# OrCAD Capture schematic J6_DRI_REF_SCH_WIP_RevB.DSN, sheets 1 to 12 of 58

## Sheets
1 SH01 - TITLE PAGE: title: Virtual J6 DRI Board; rev: B; note: tbd
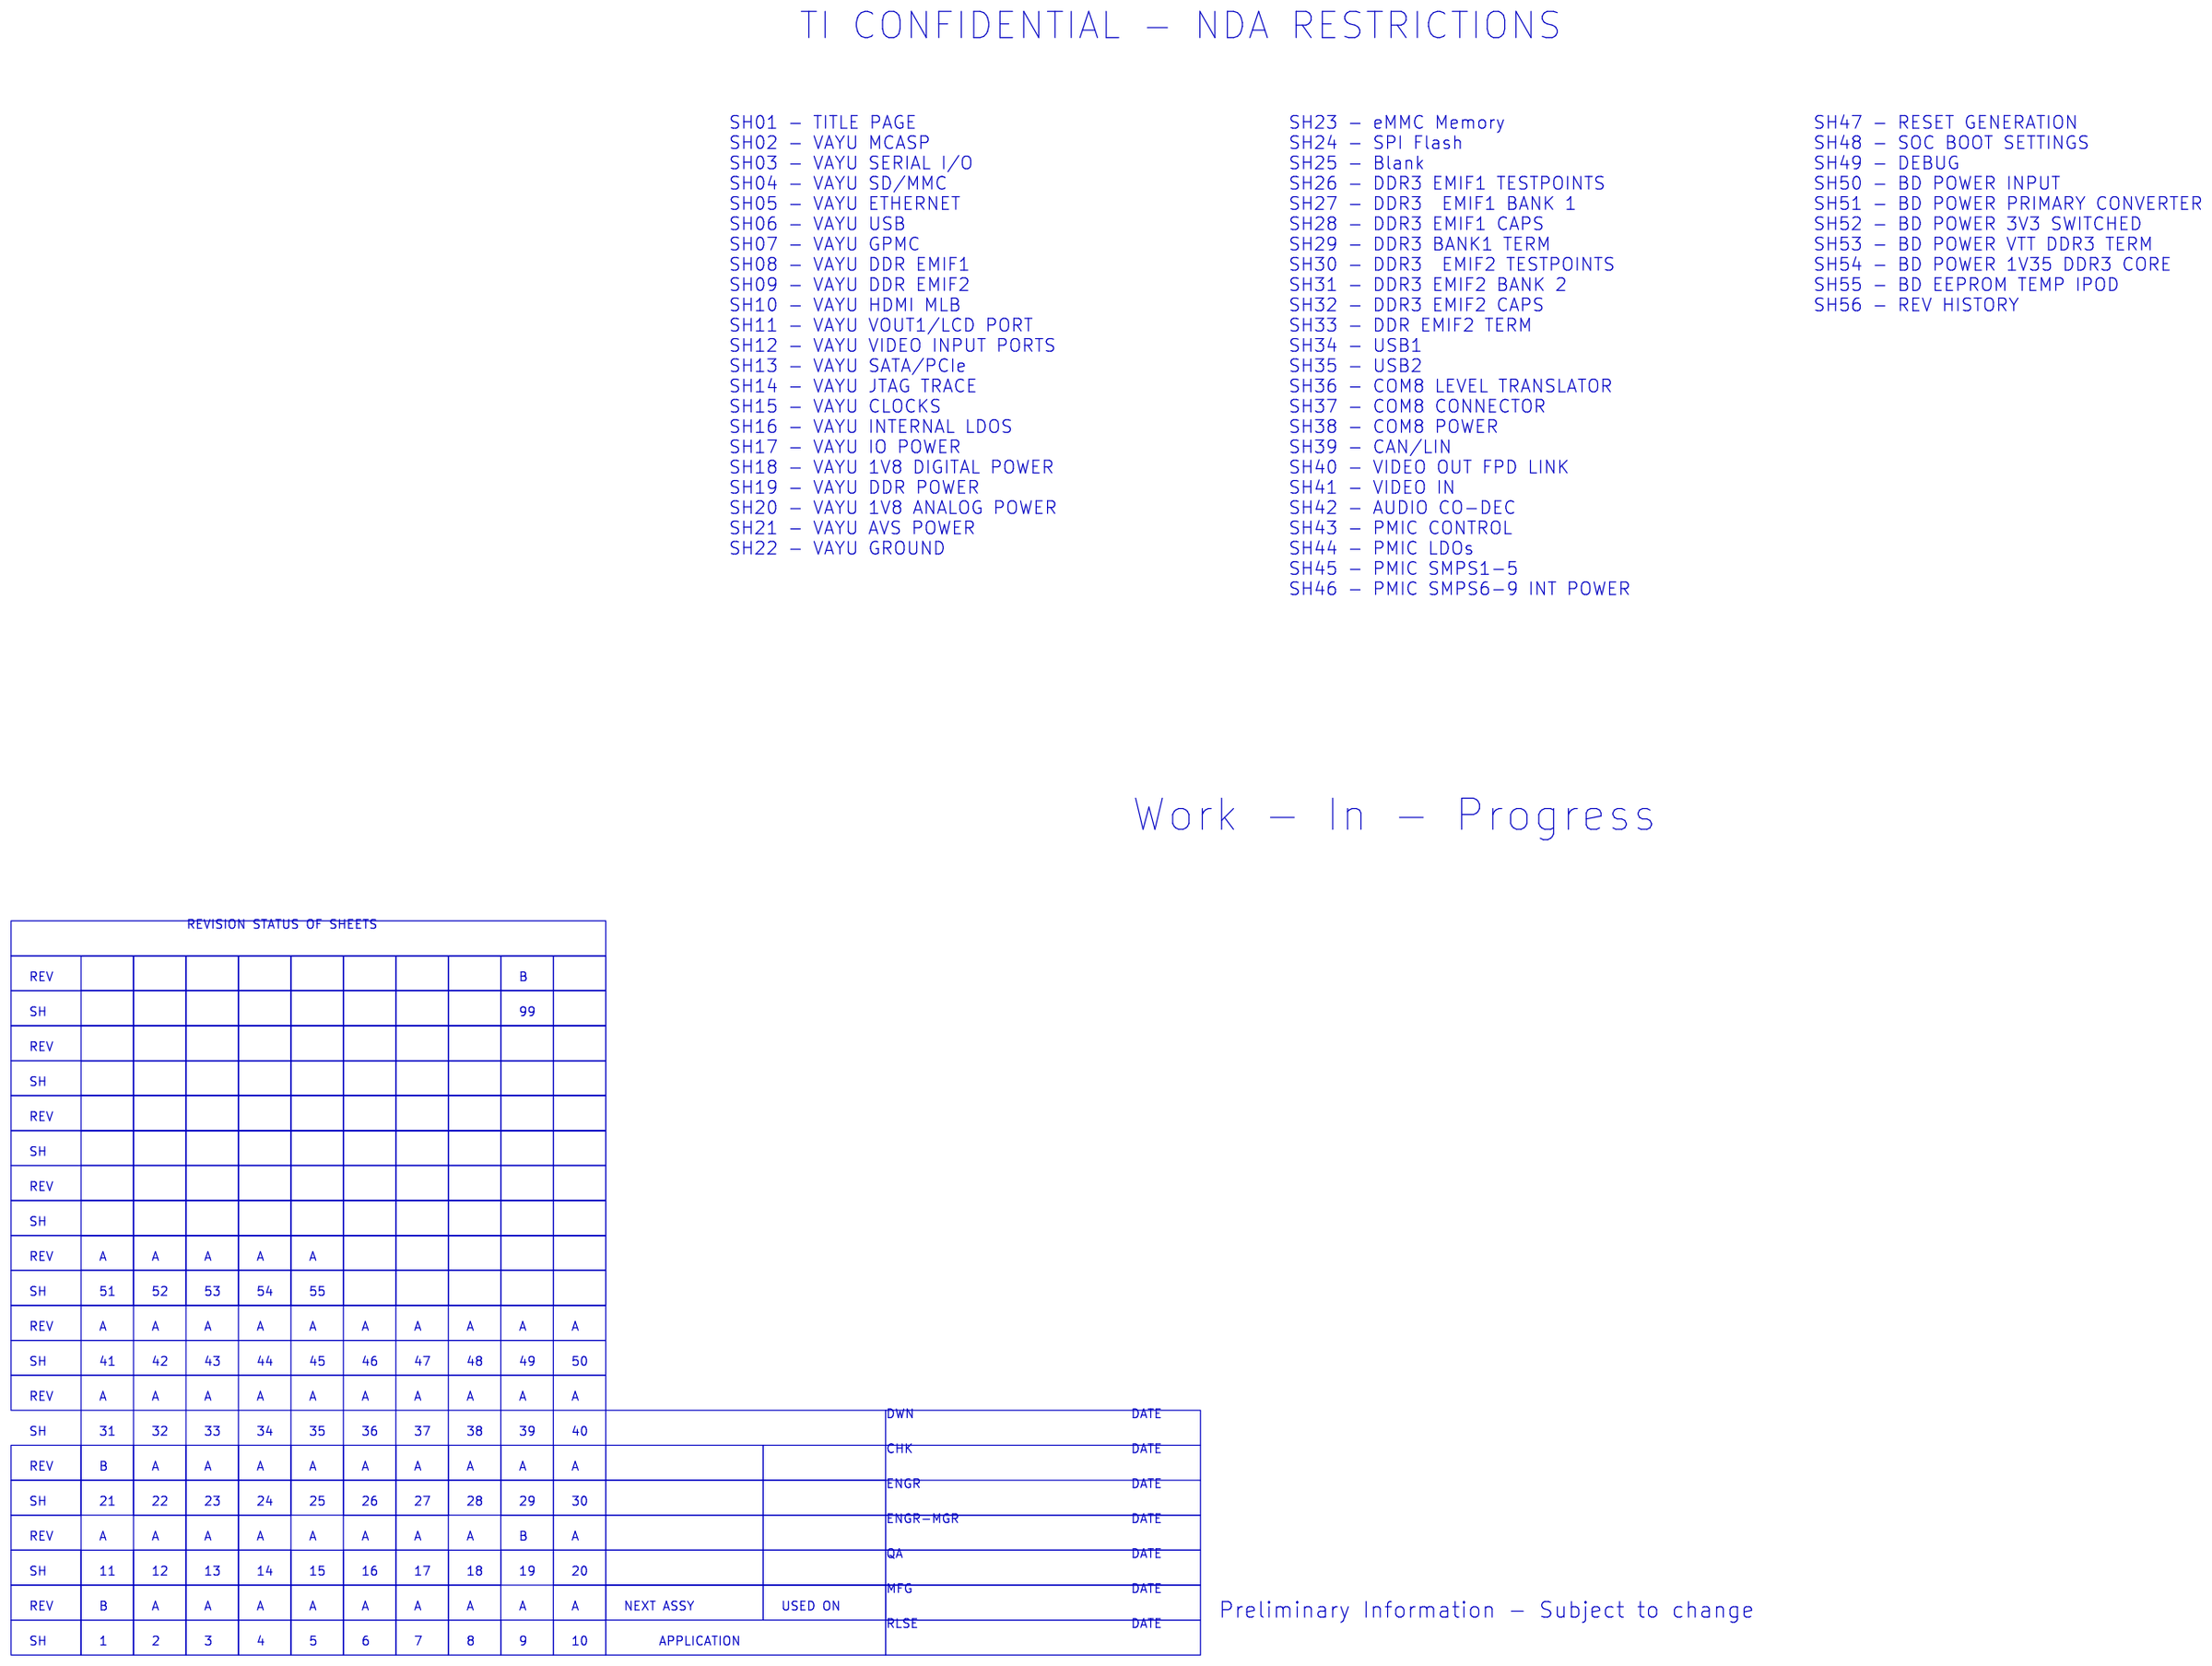
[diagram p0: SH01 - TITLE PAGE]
2 SH02 - VAYU MCASP: size B; rev: A
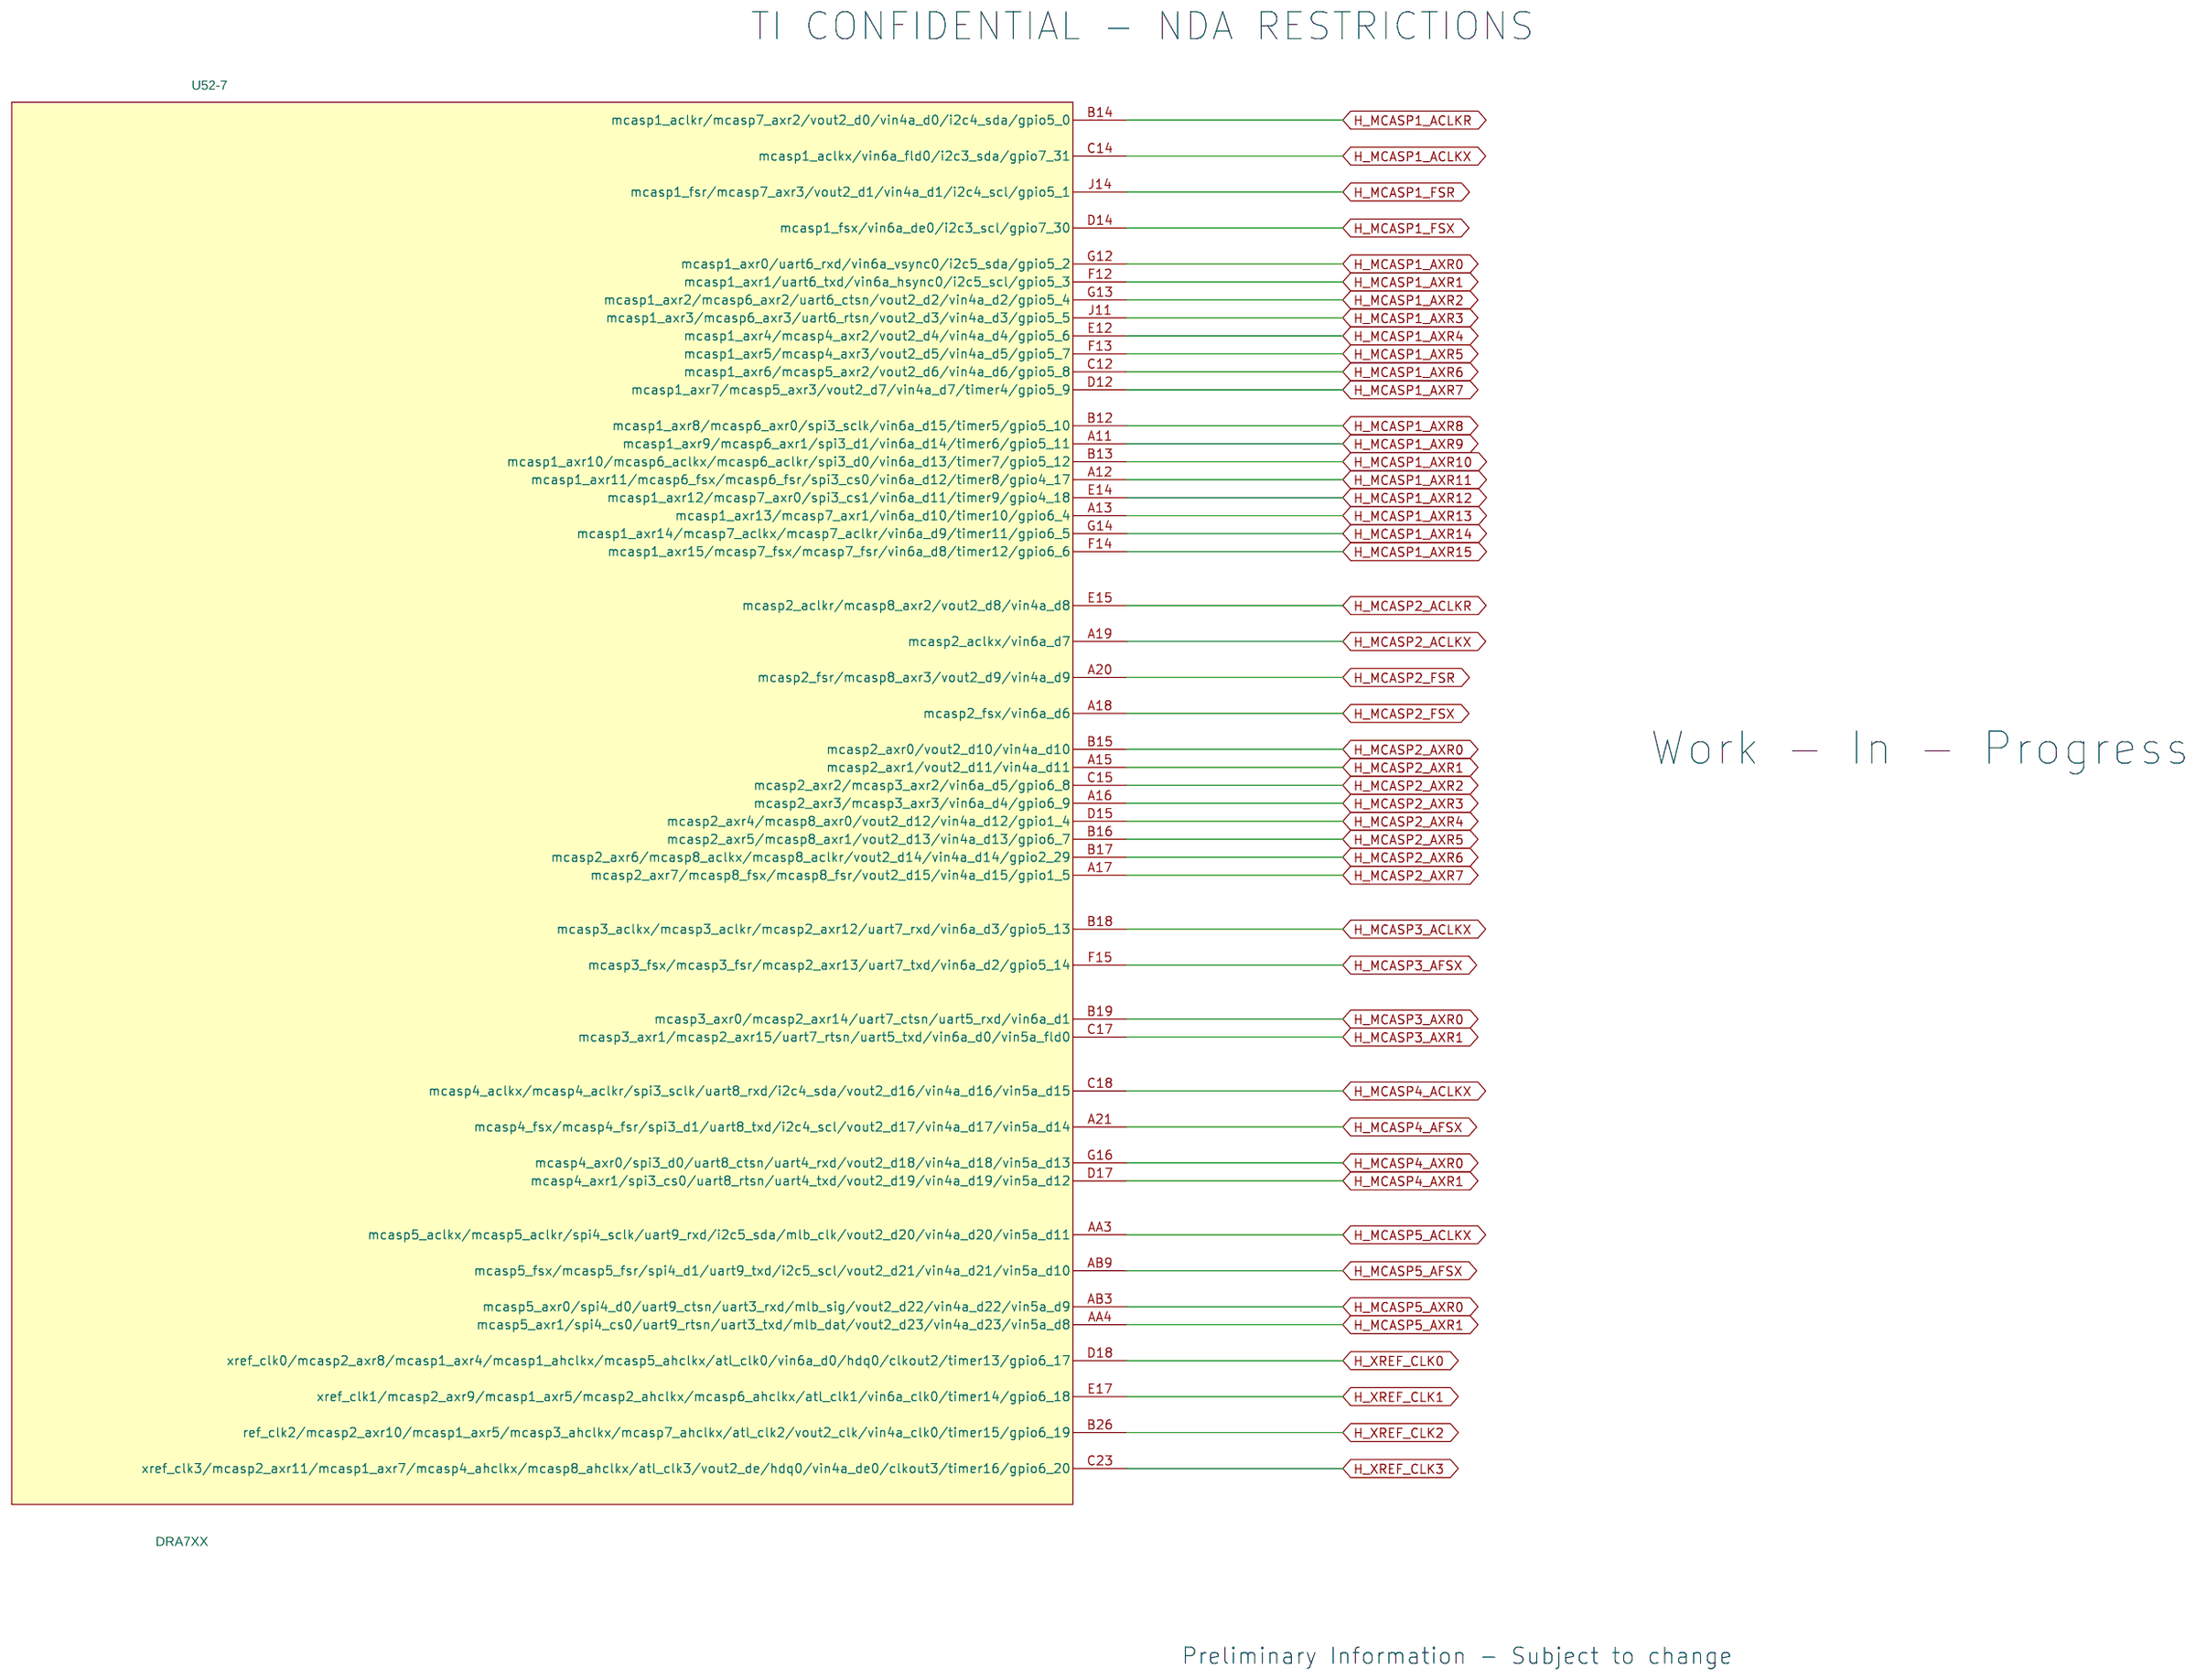
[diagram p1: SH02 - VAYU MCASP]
3 SH04 - VAYU SD MMC: size B; rev: A
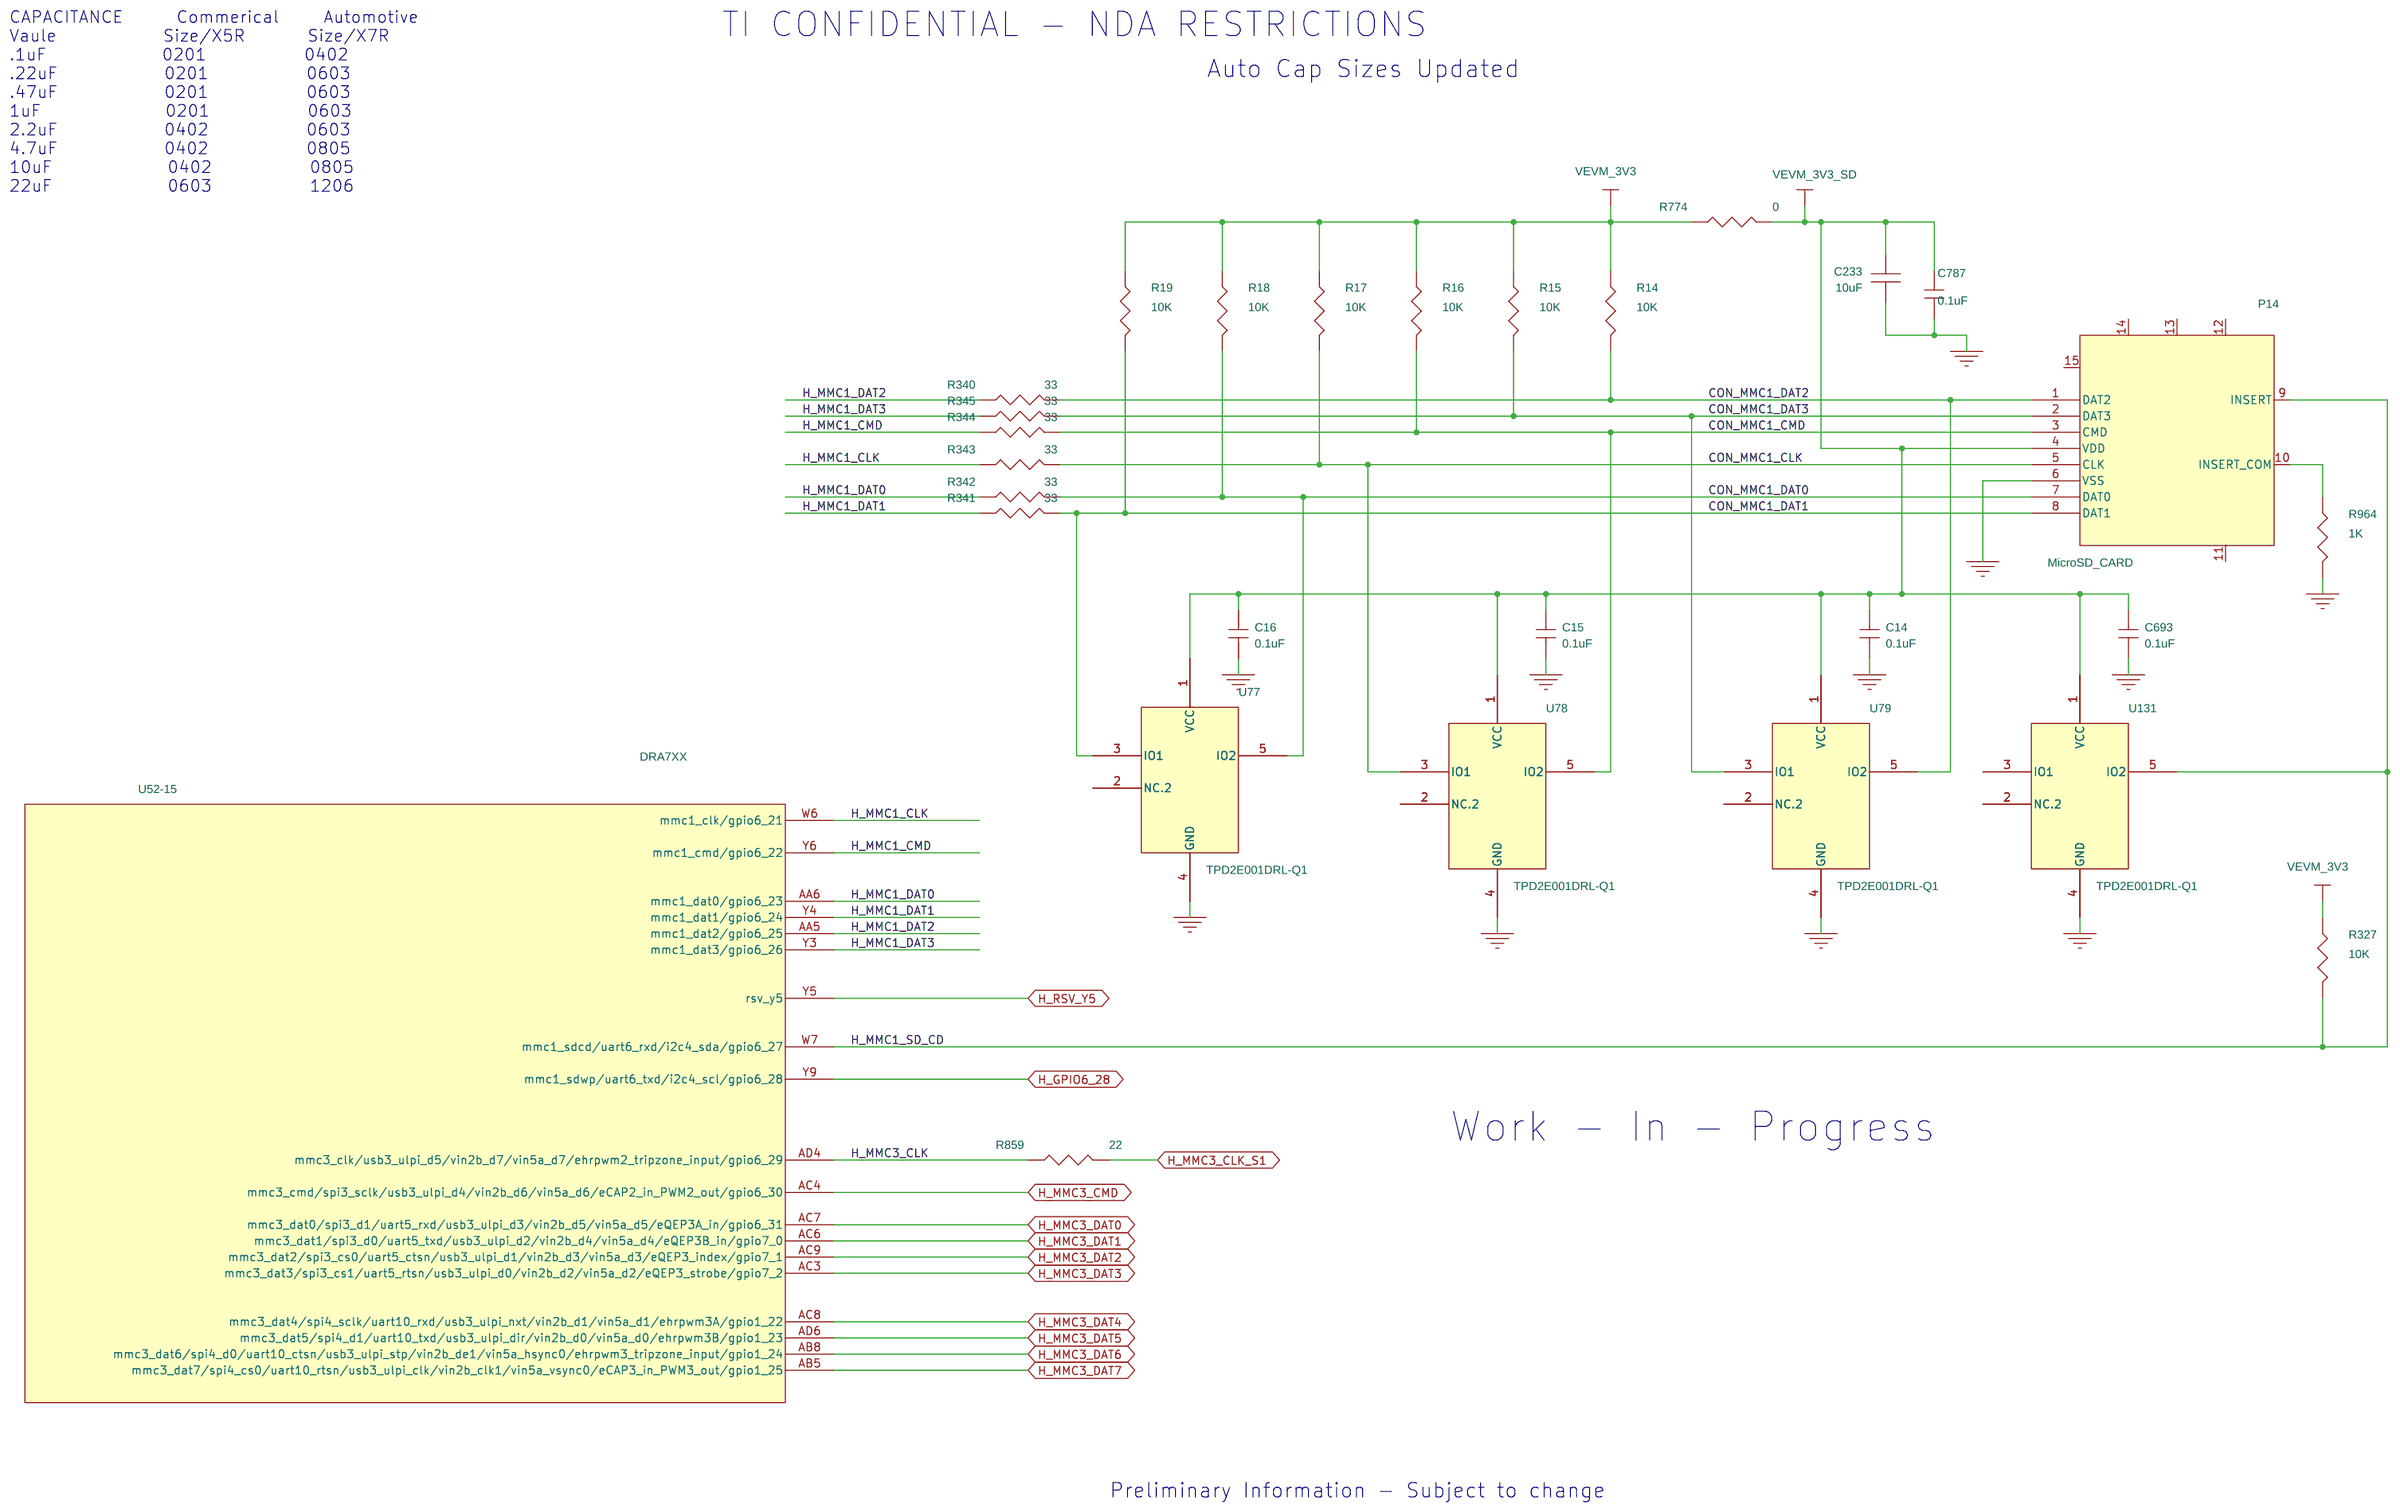
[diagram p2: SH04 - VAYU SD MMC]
4 SH05 - VAYU ETHERNET: size B; rev: A
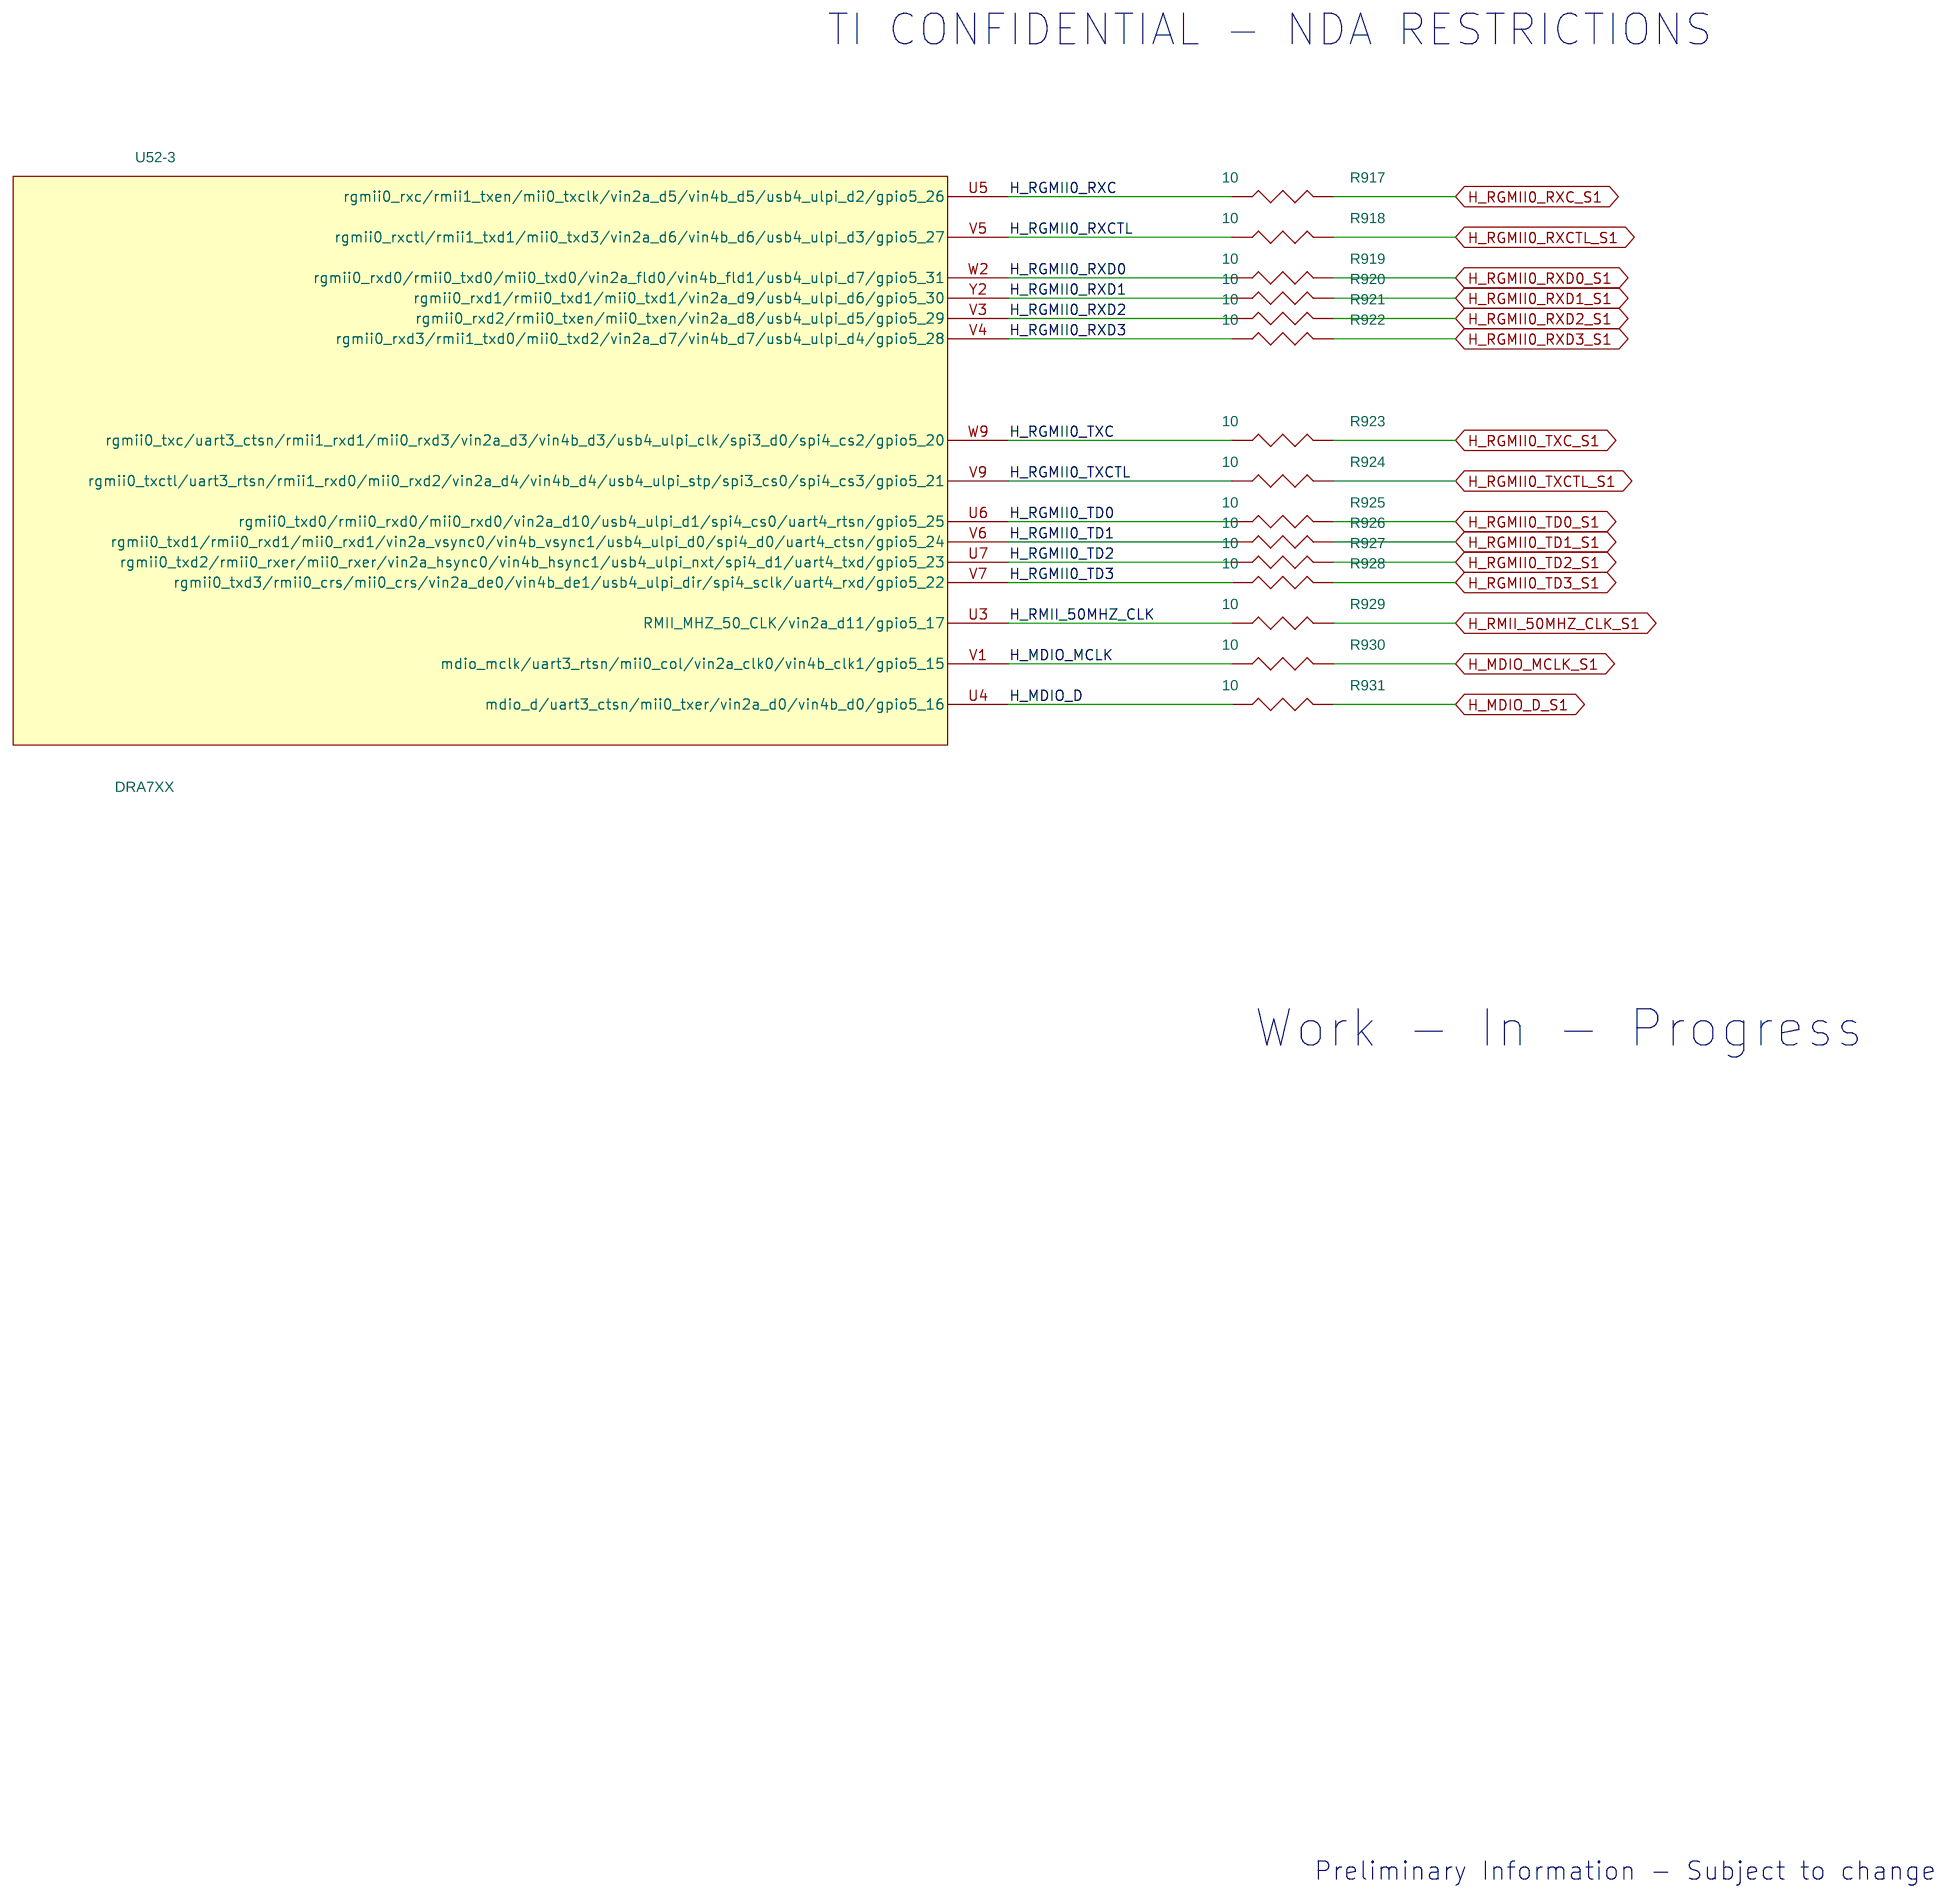
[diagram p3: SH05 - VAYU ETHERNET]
5 SH06 - VAYU USB: size B; rev: A
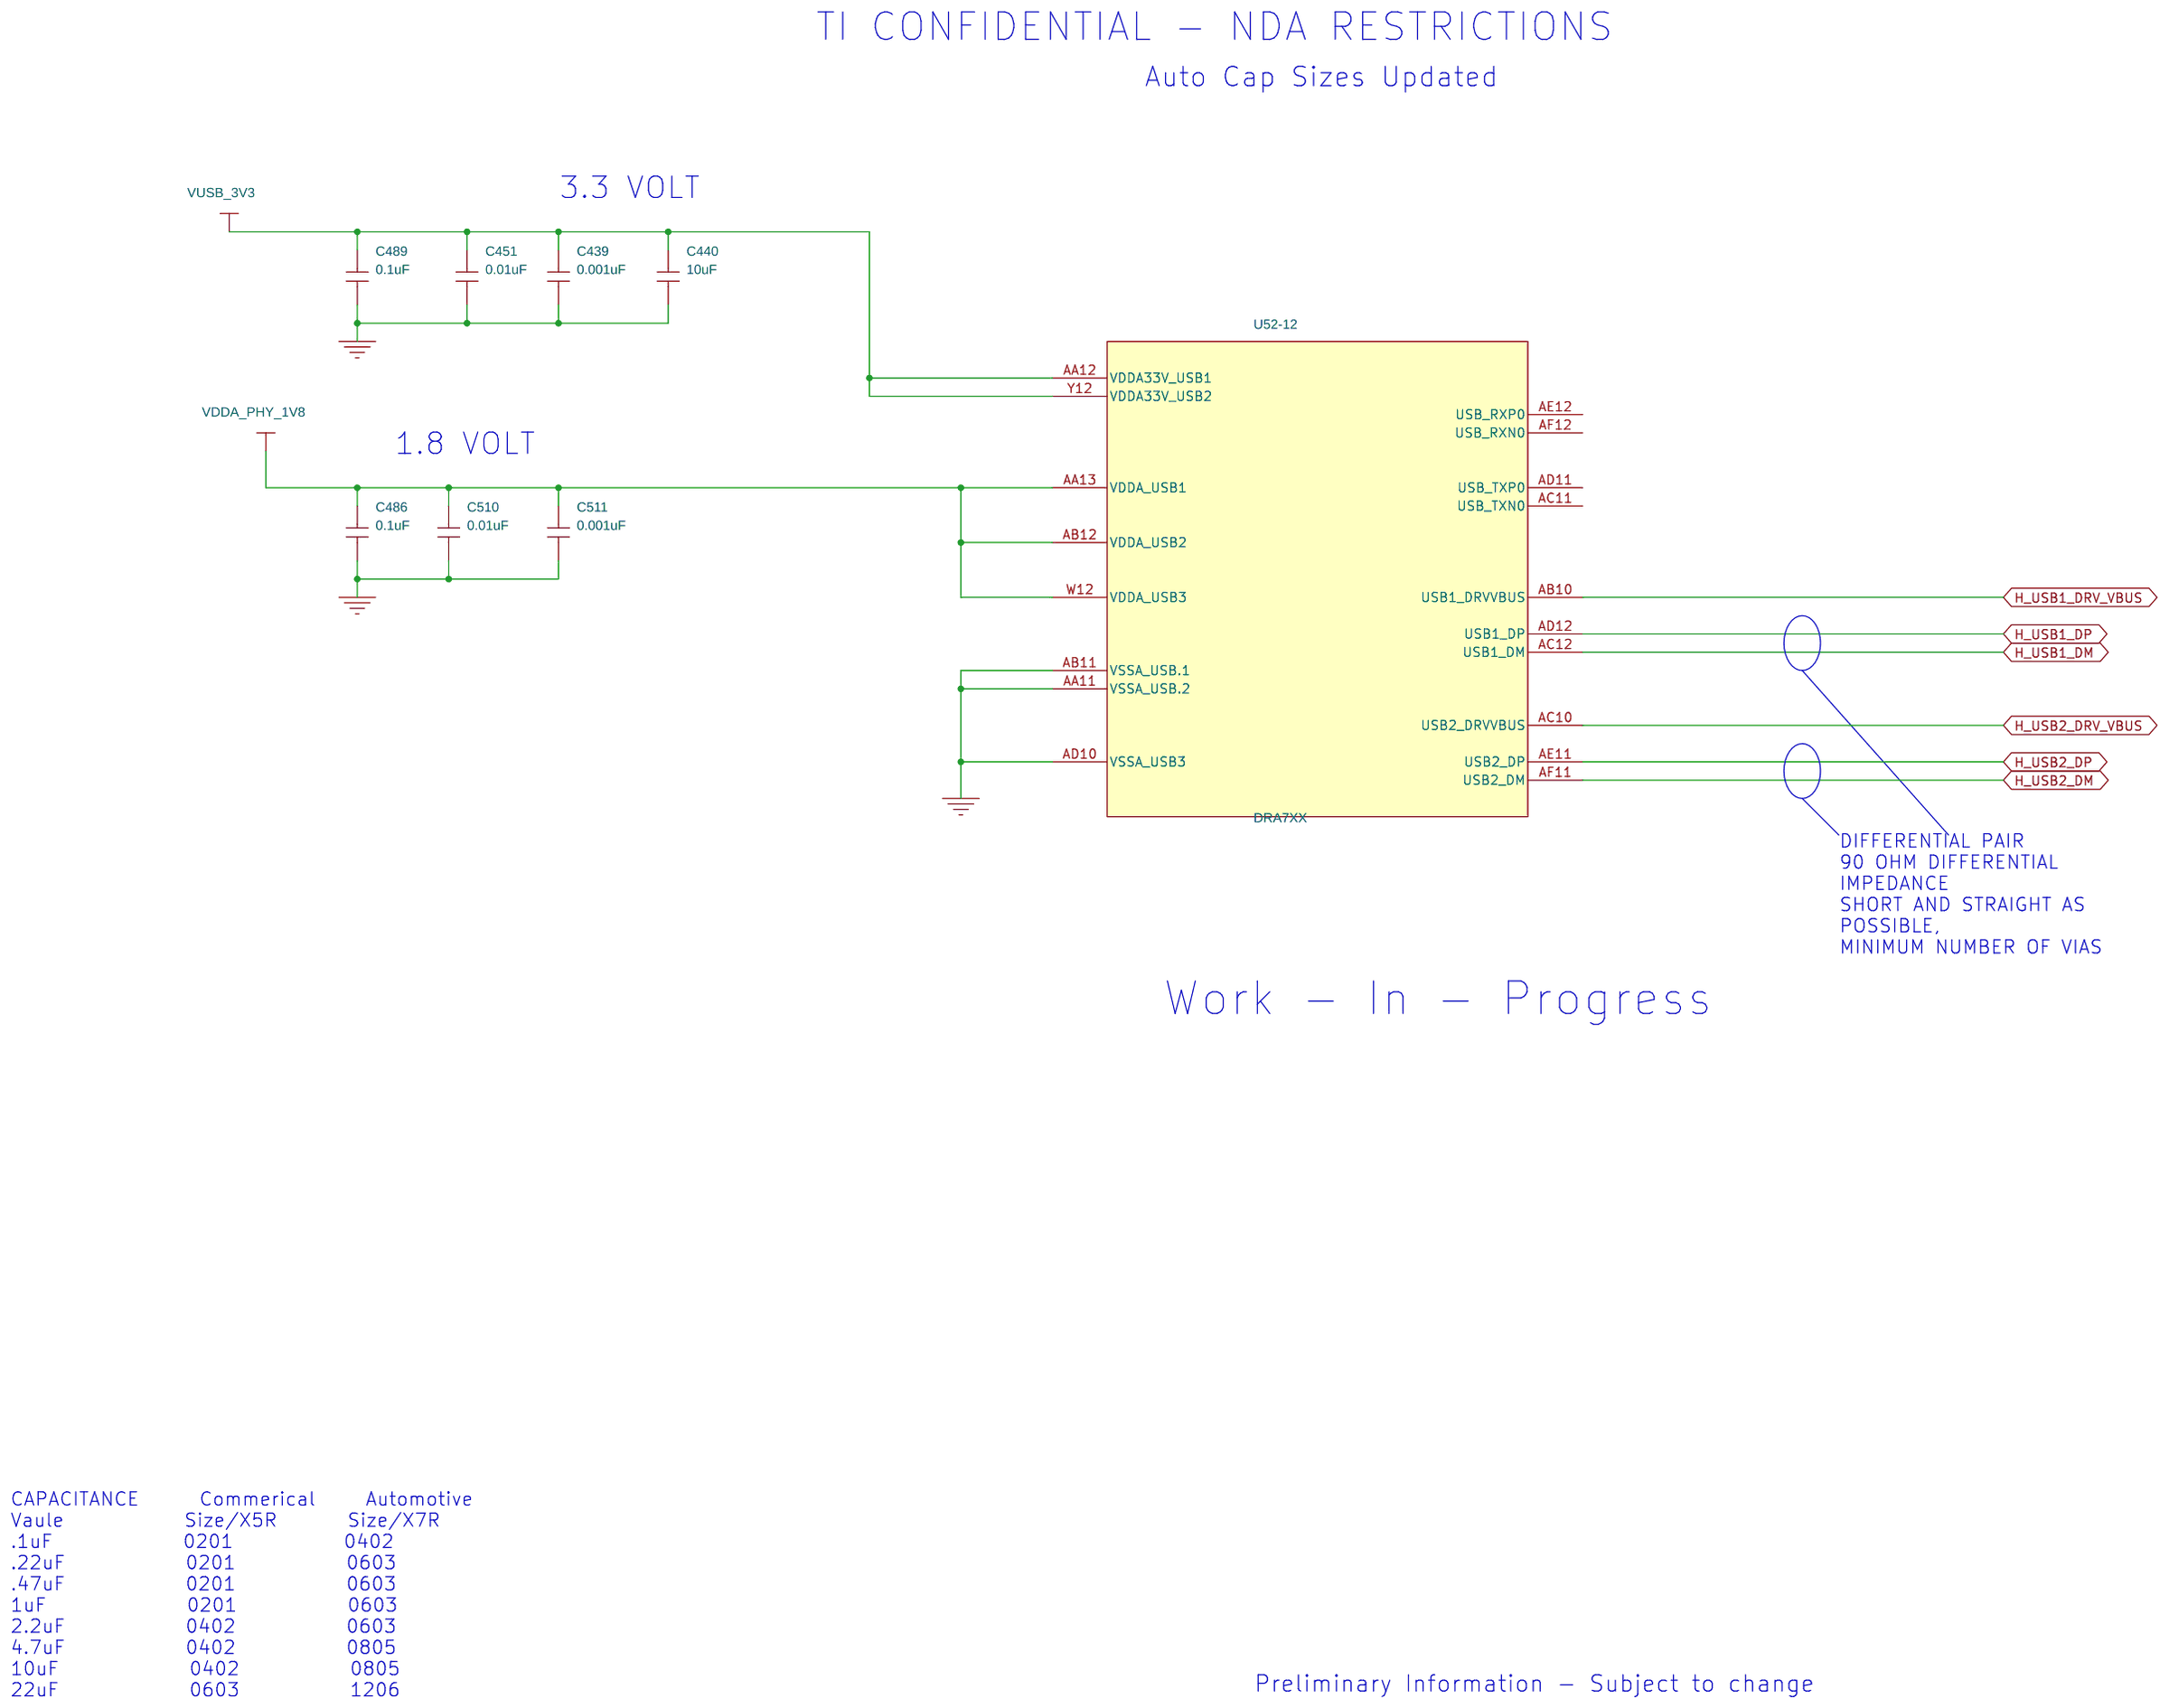
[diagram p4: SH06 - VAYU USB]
6 SH07 - VAYU GPMC: size B; rev: A
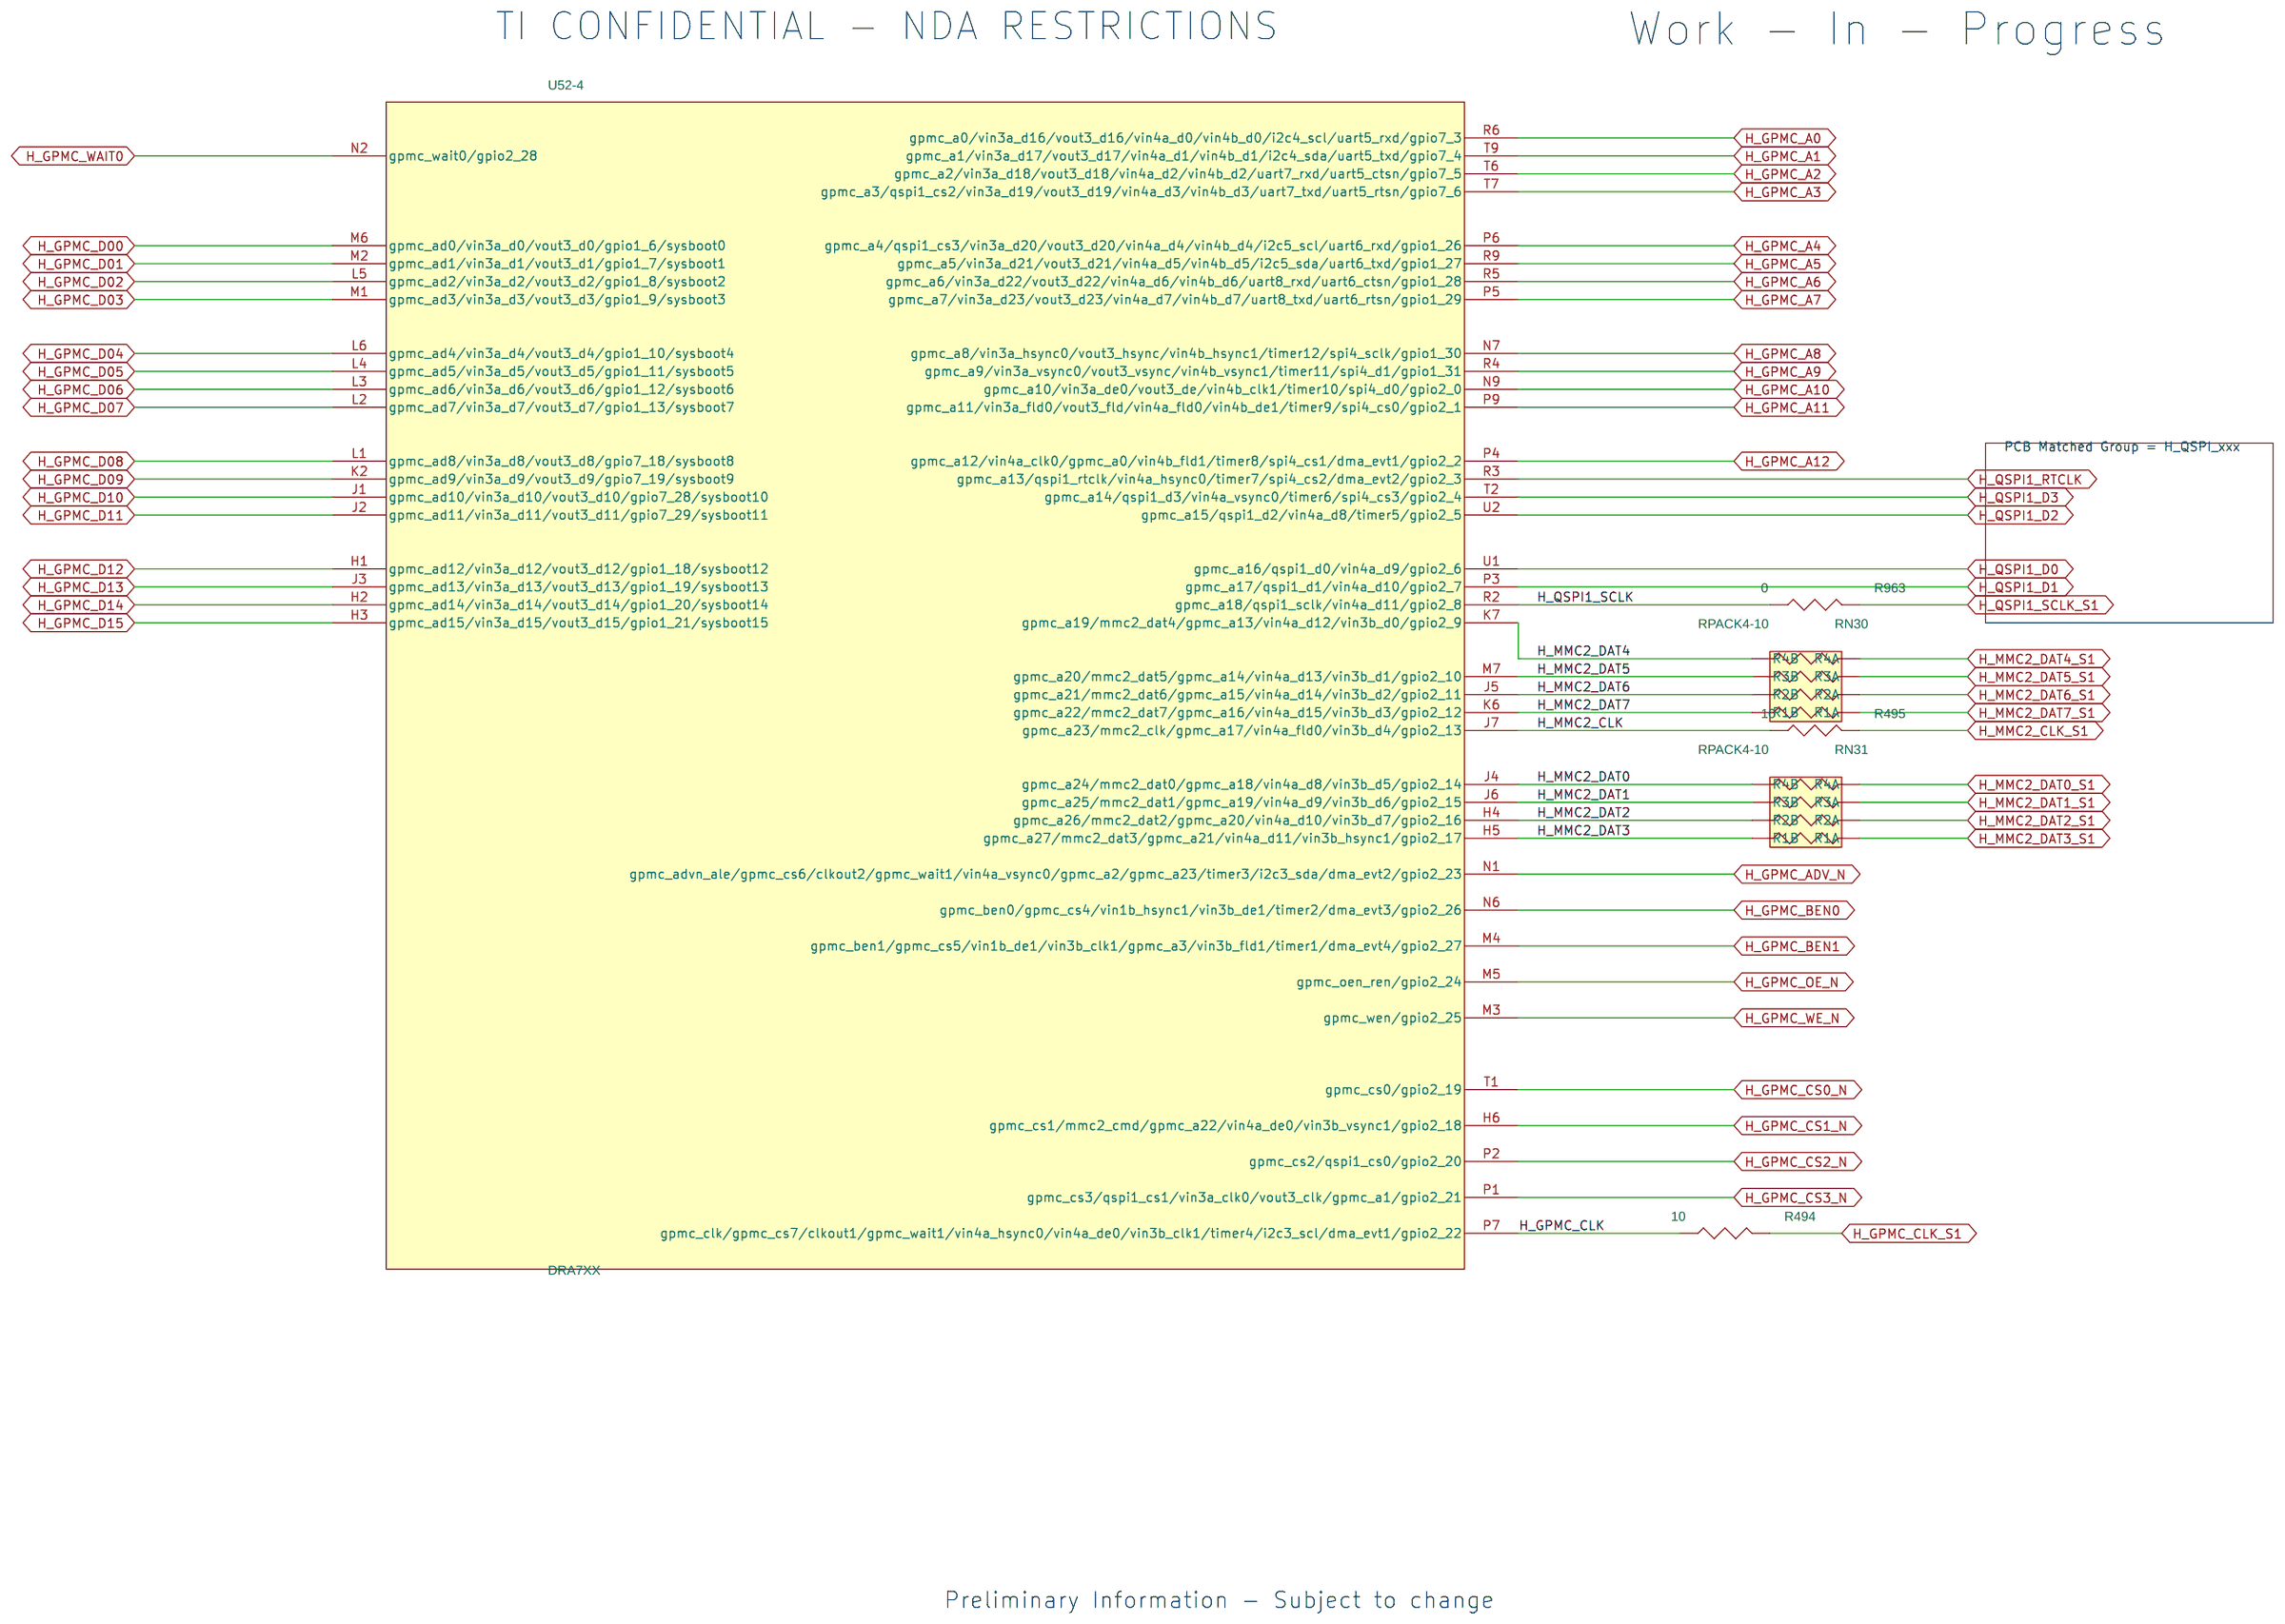
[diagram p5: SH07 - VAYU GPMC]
7 SH08 - VAYU DDR EMIF1: size B; rev: A
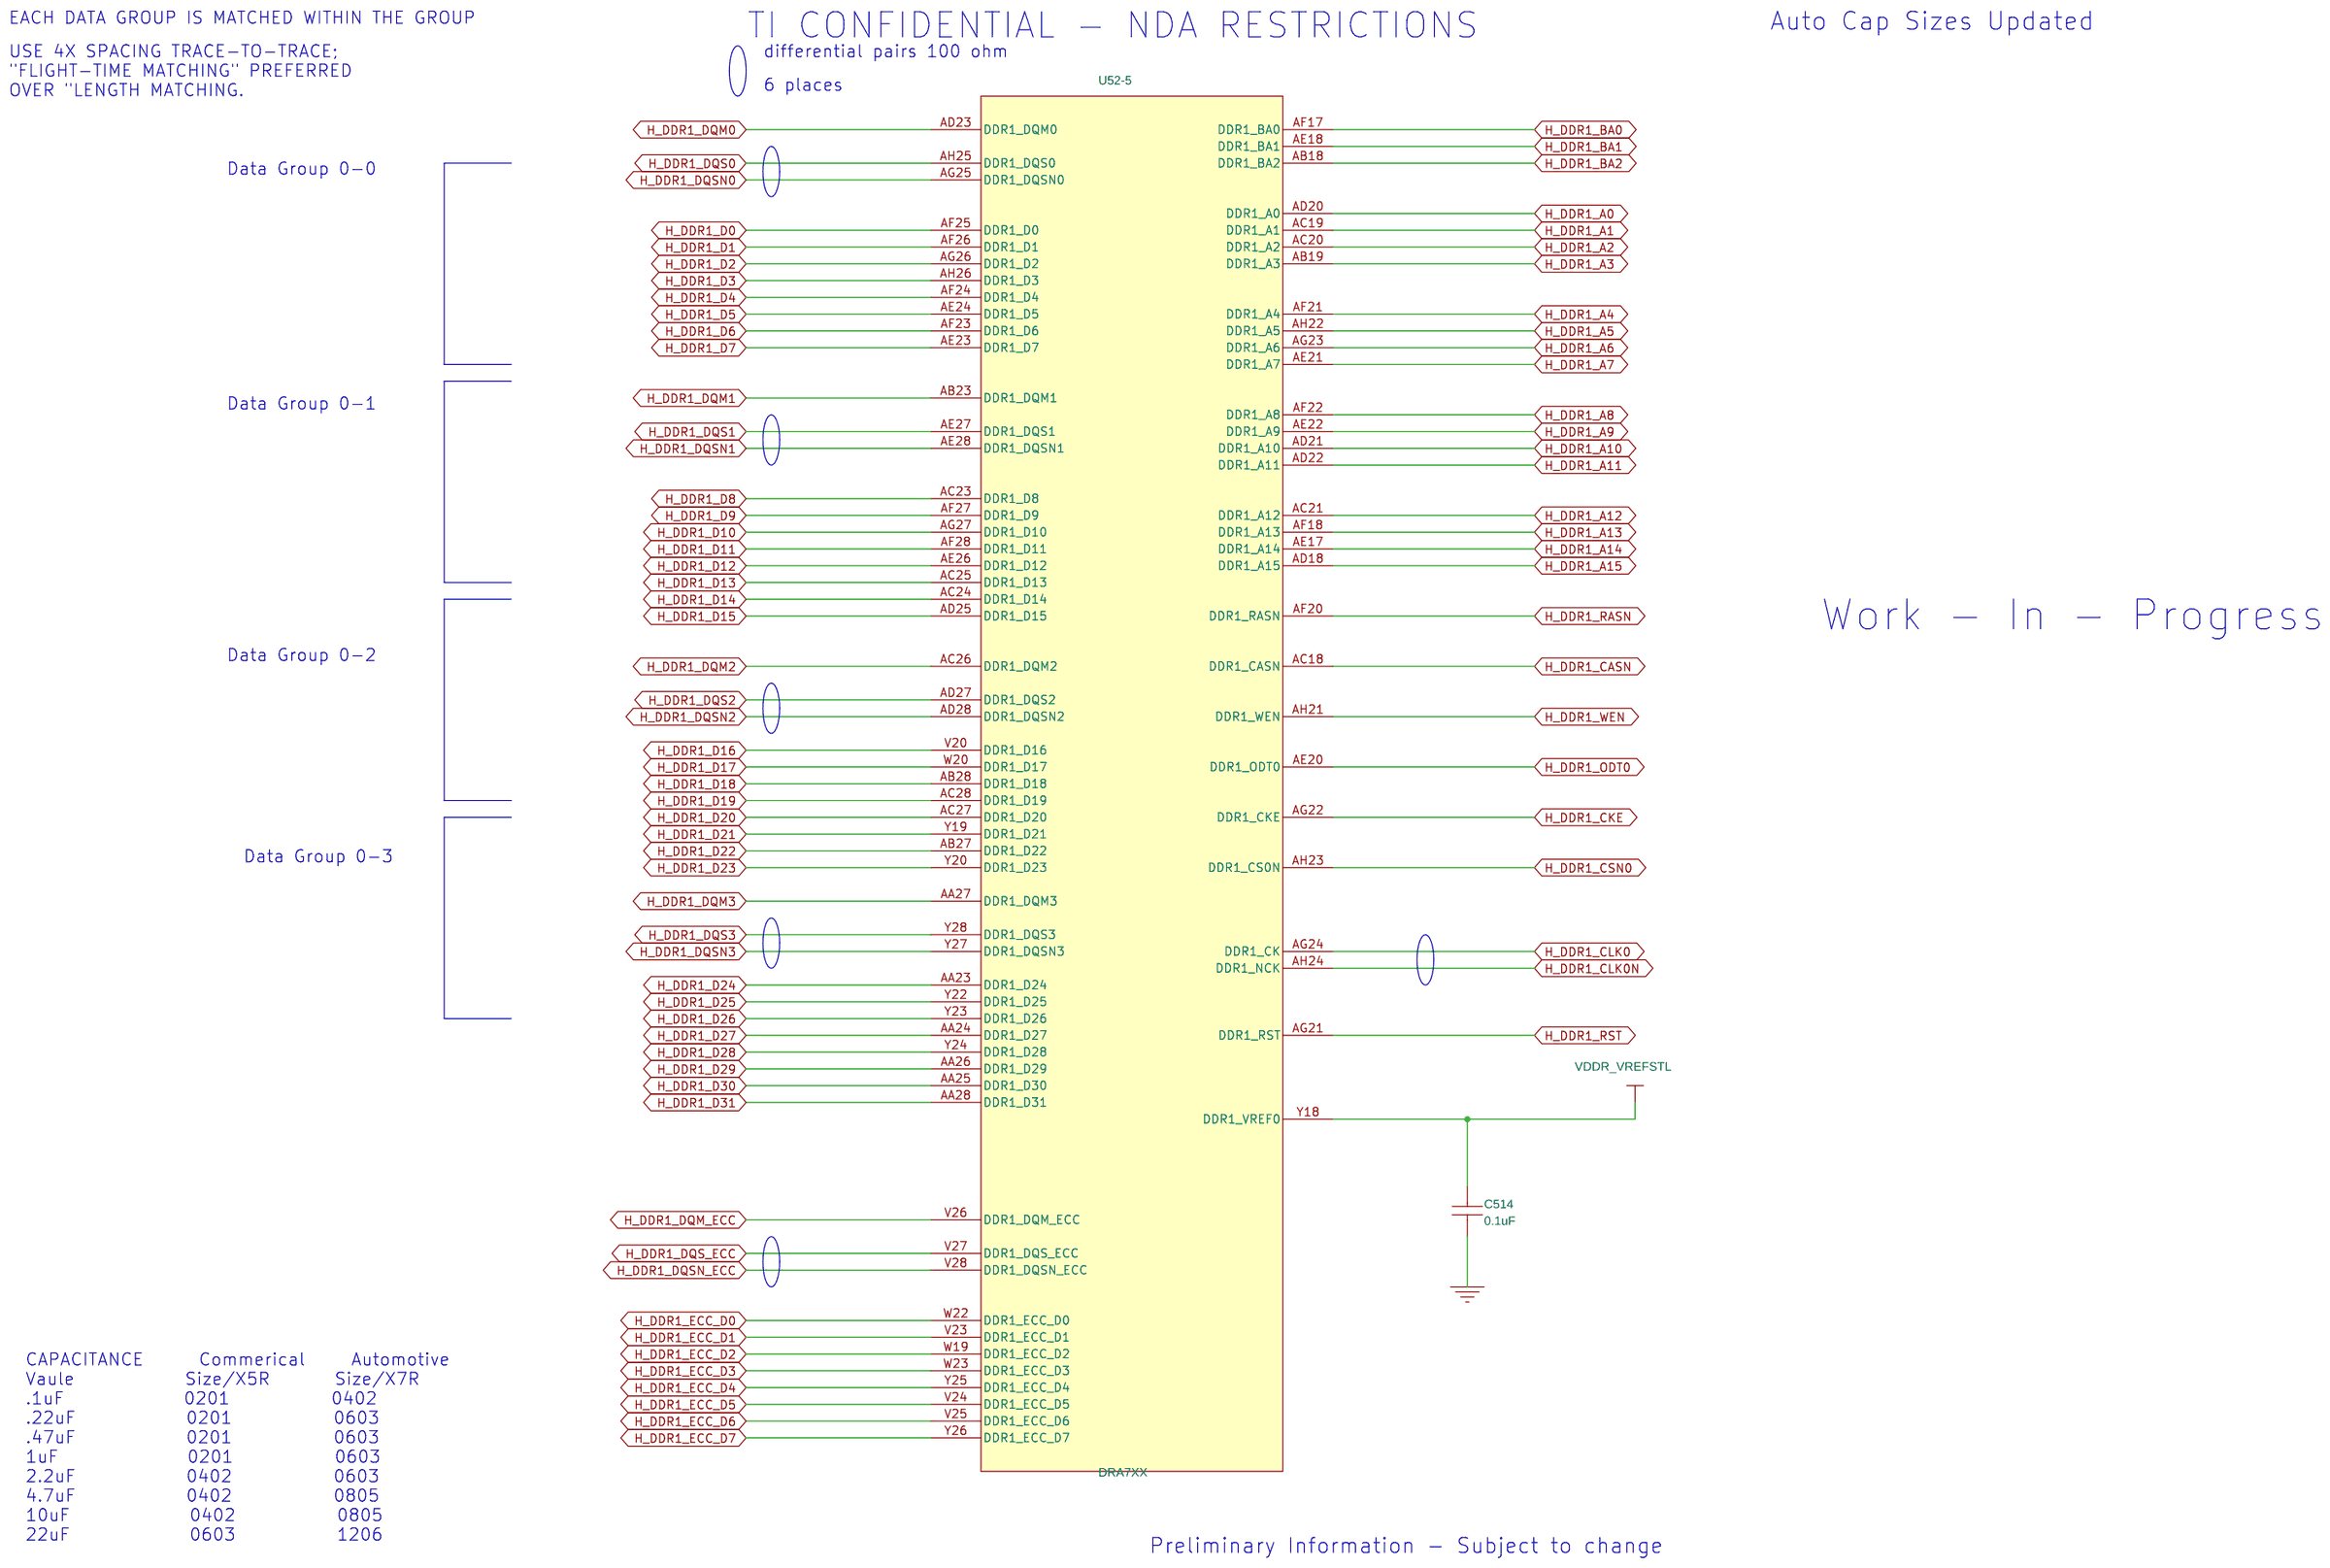
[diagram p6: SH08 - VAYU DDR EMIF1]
8 SH09 - VAYU DDR EMIF2: size B; rev: A
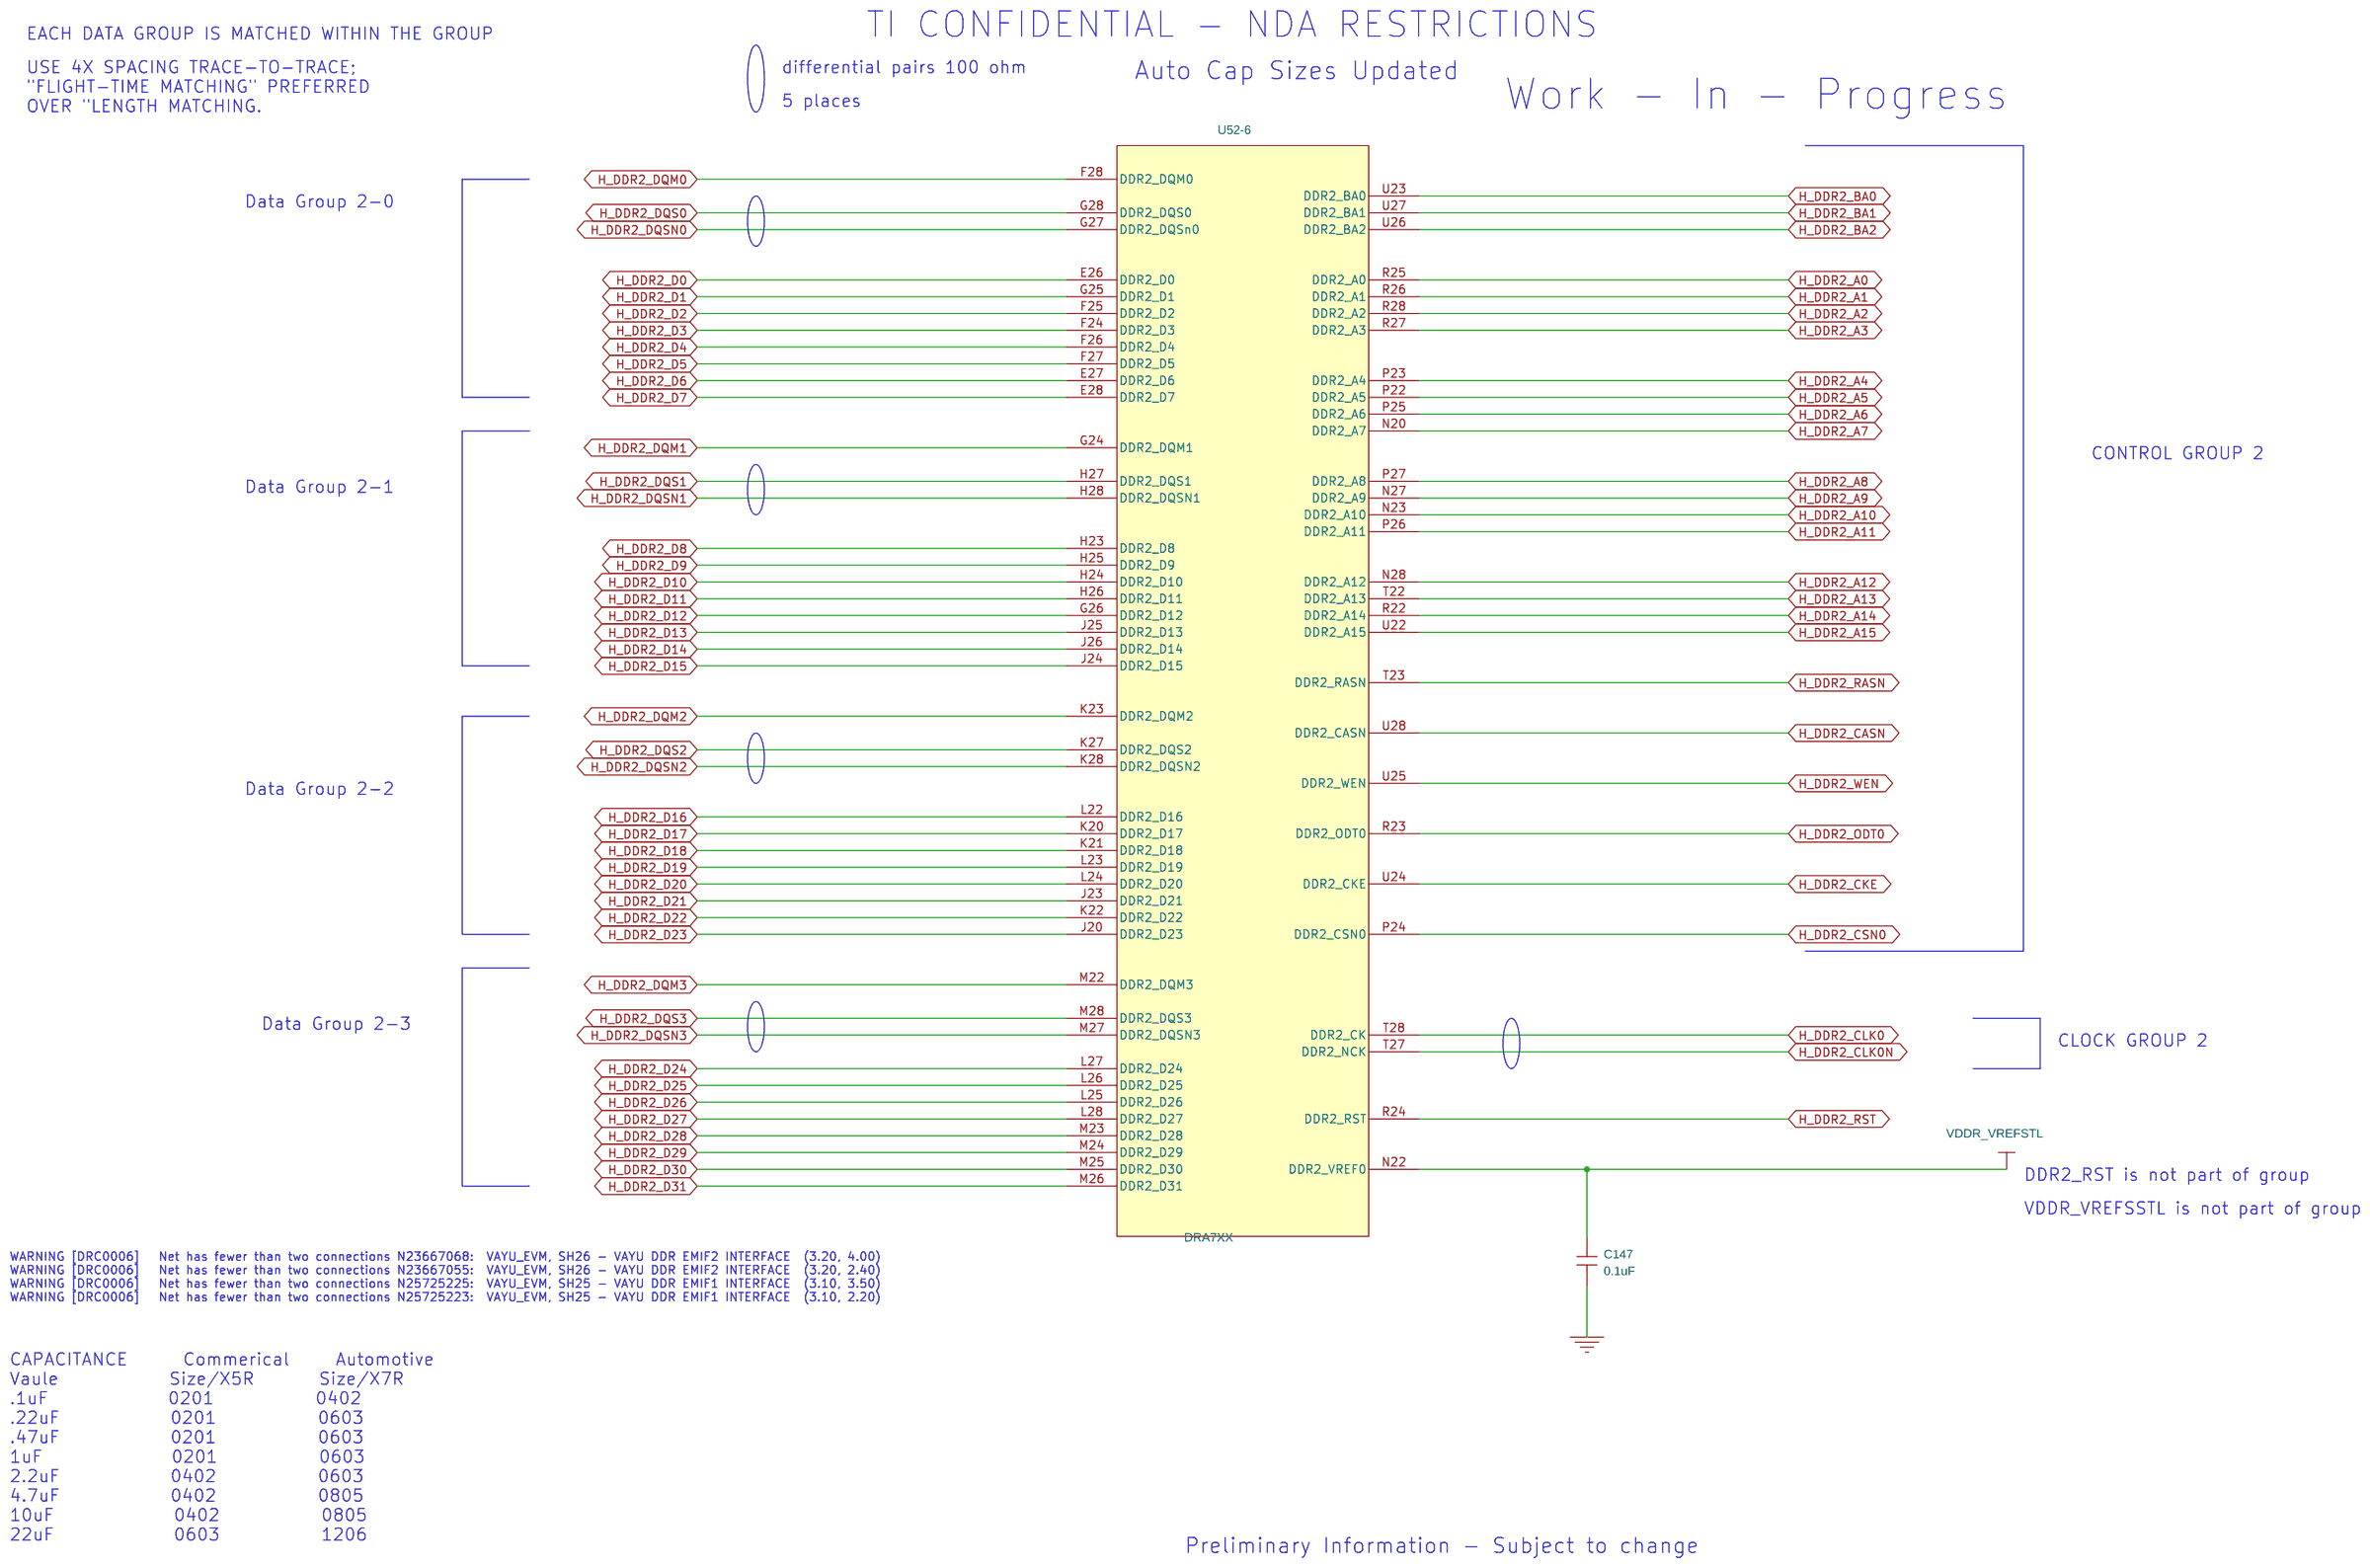
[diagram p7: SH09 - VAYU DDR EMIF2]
9 SH10 - VAYU HDMI MLB: size B; rev: A
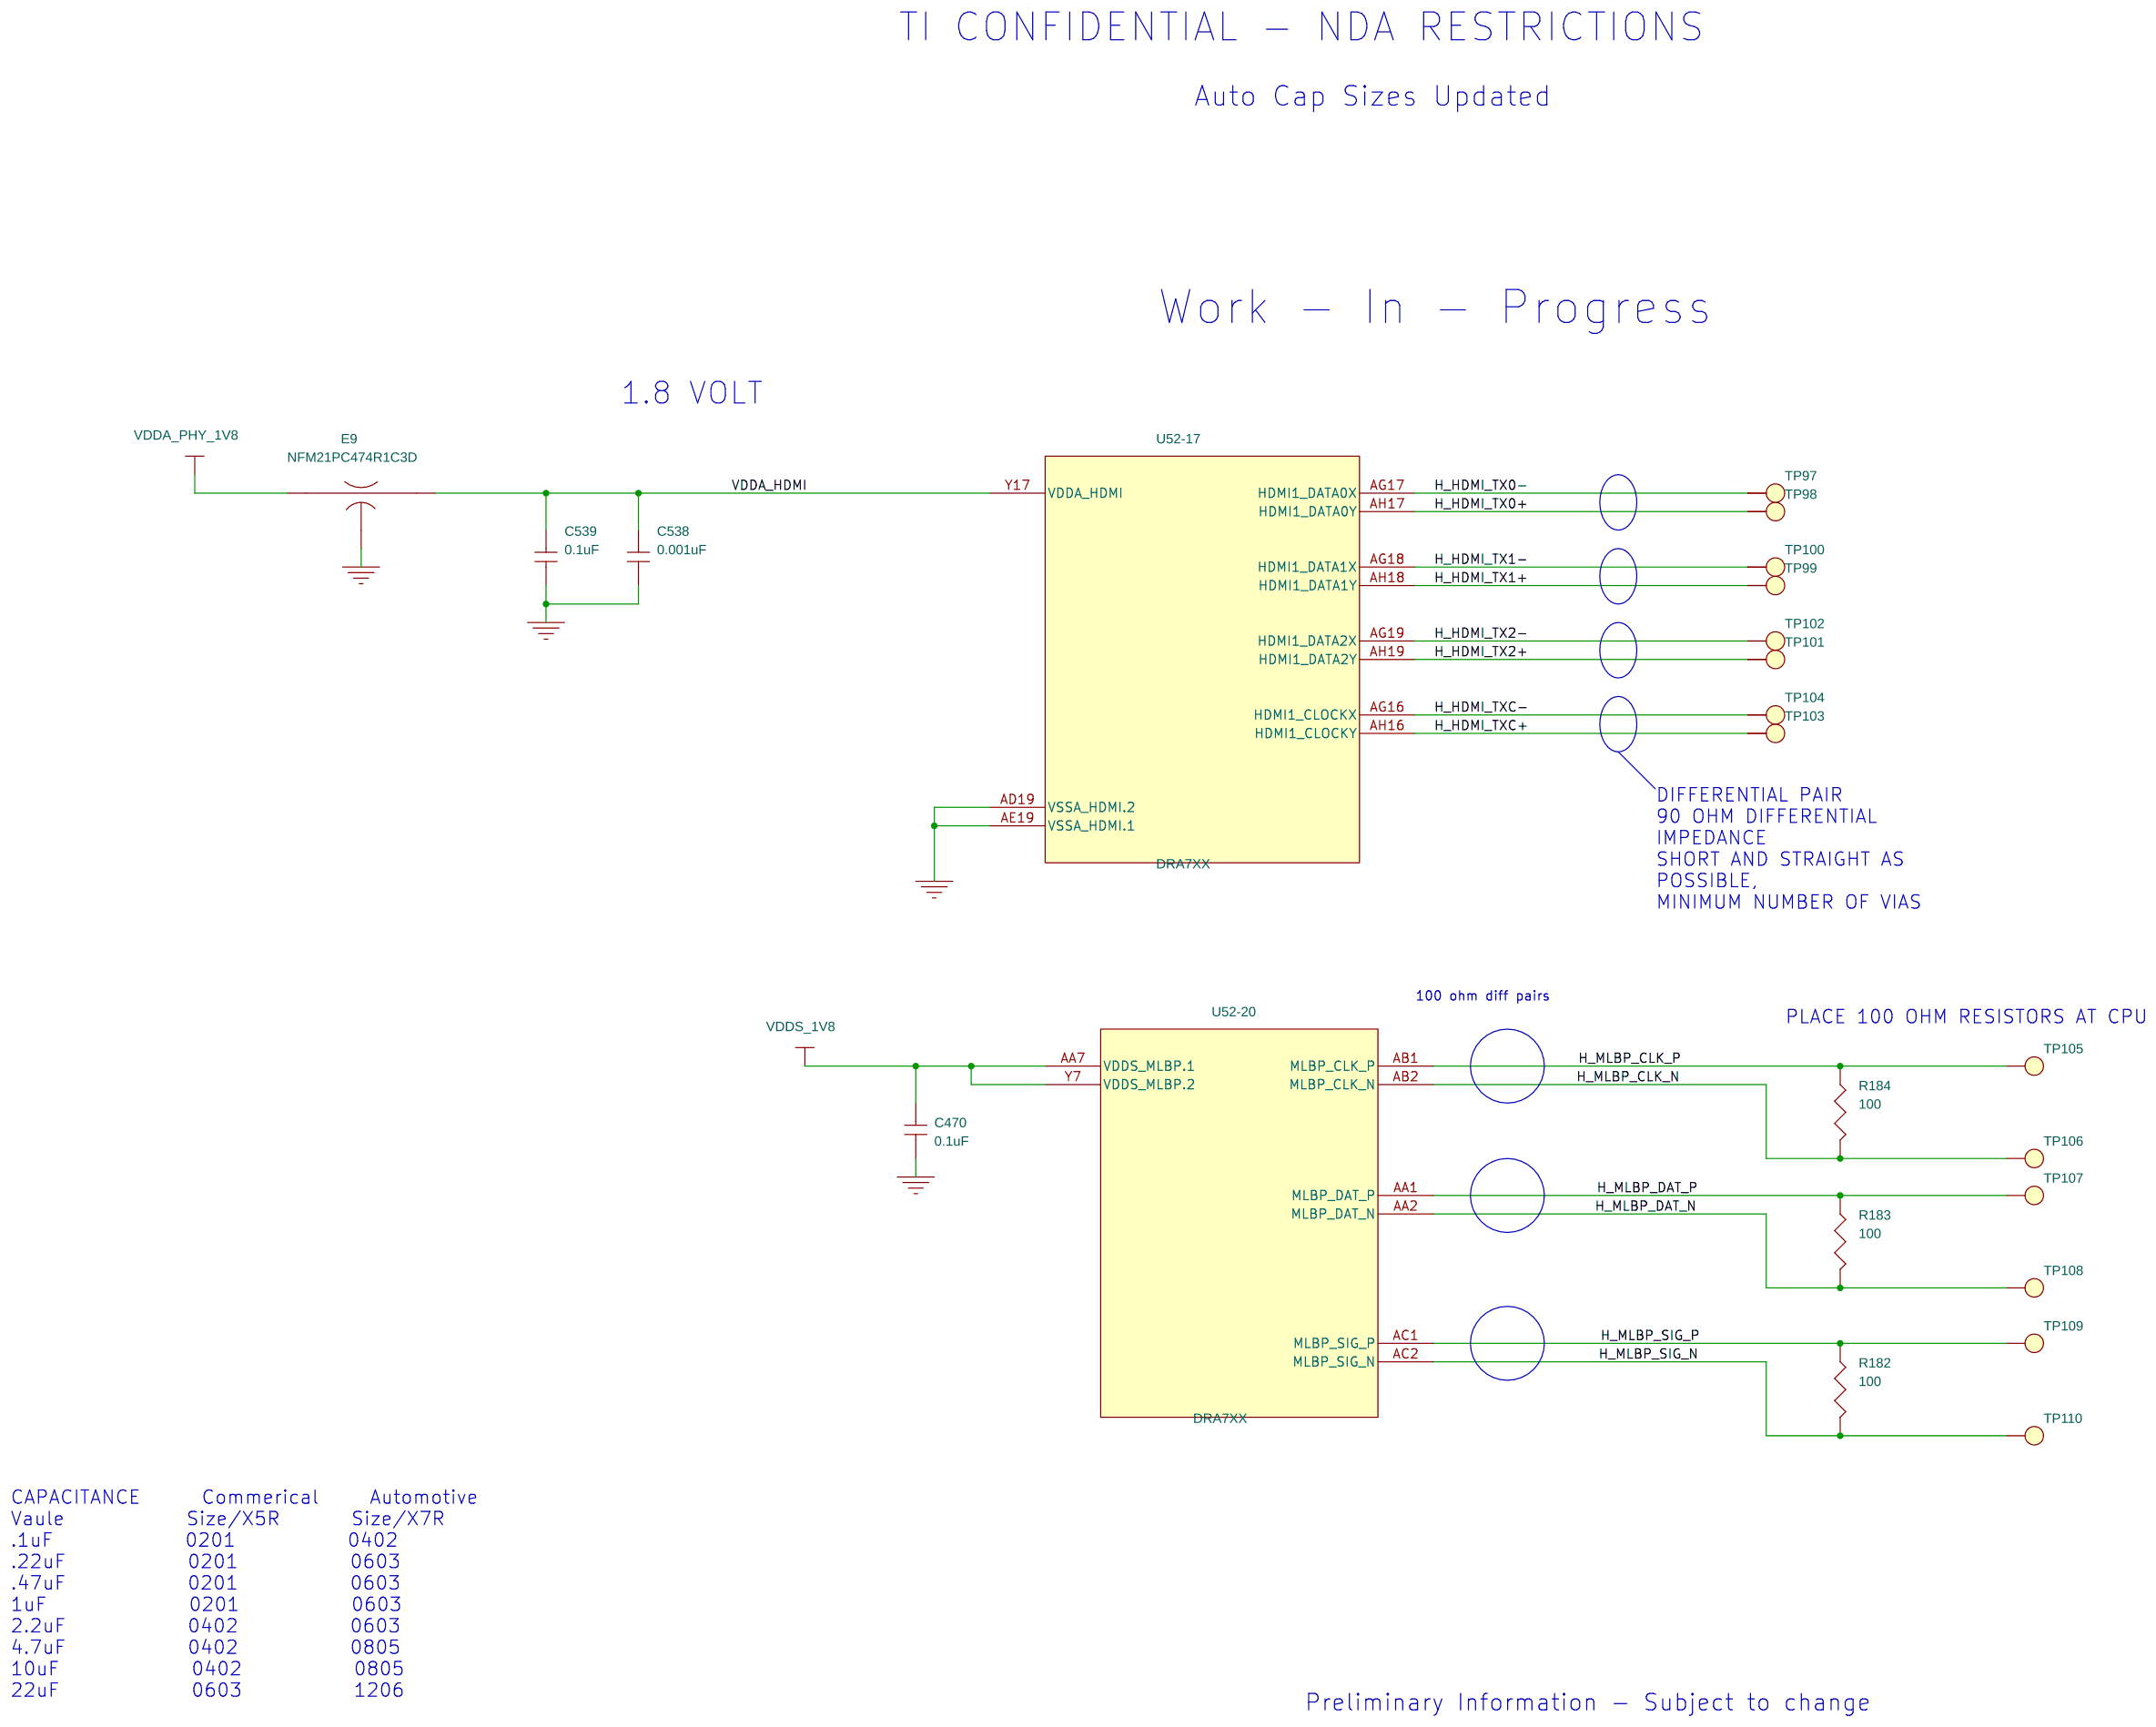
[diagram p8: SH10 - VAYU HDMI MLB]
10 SH12 - VAYU VIDEO INPUT PORTS: size B; rev: A
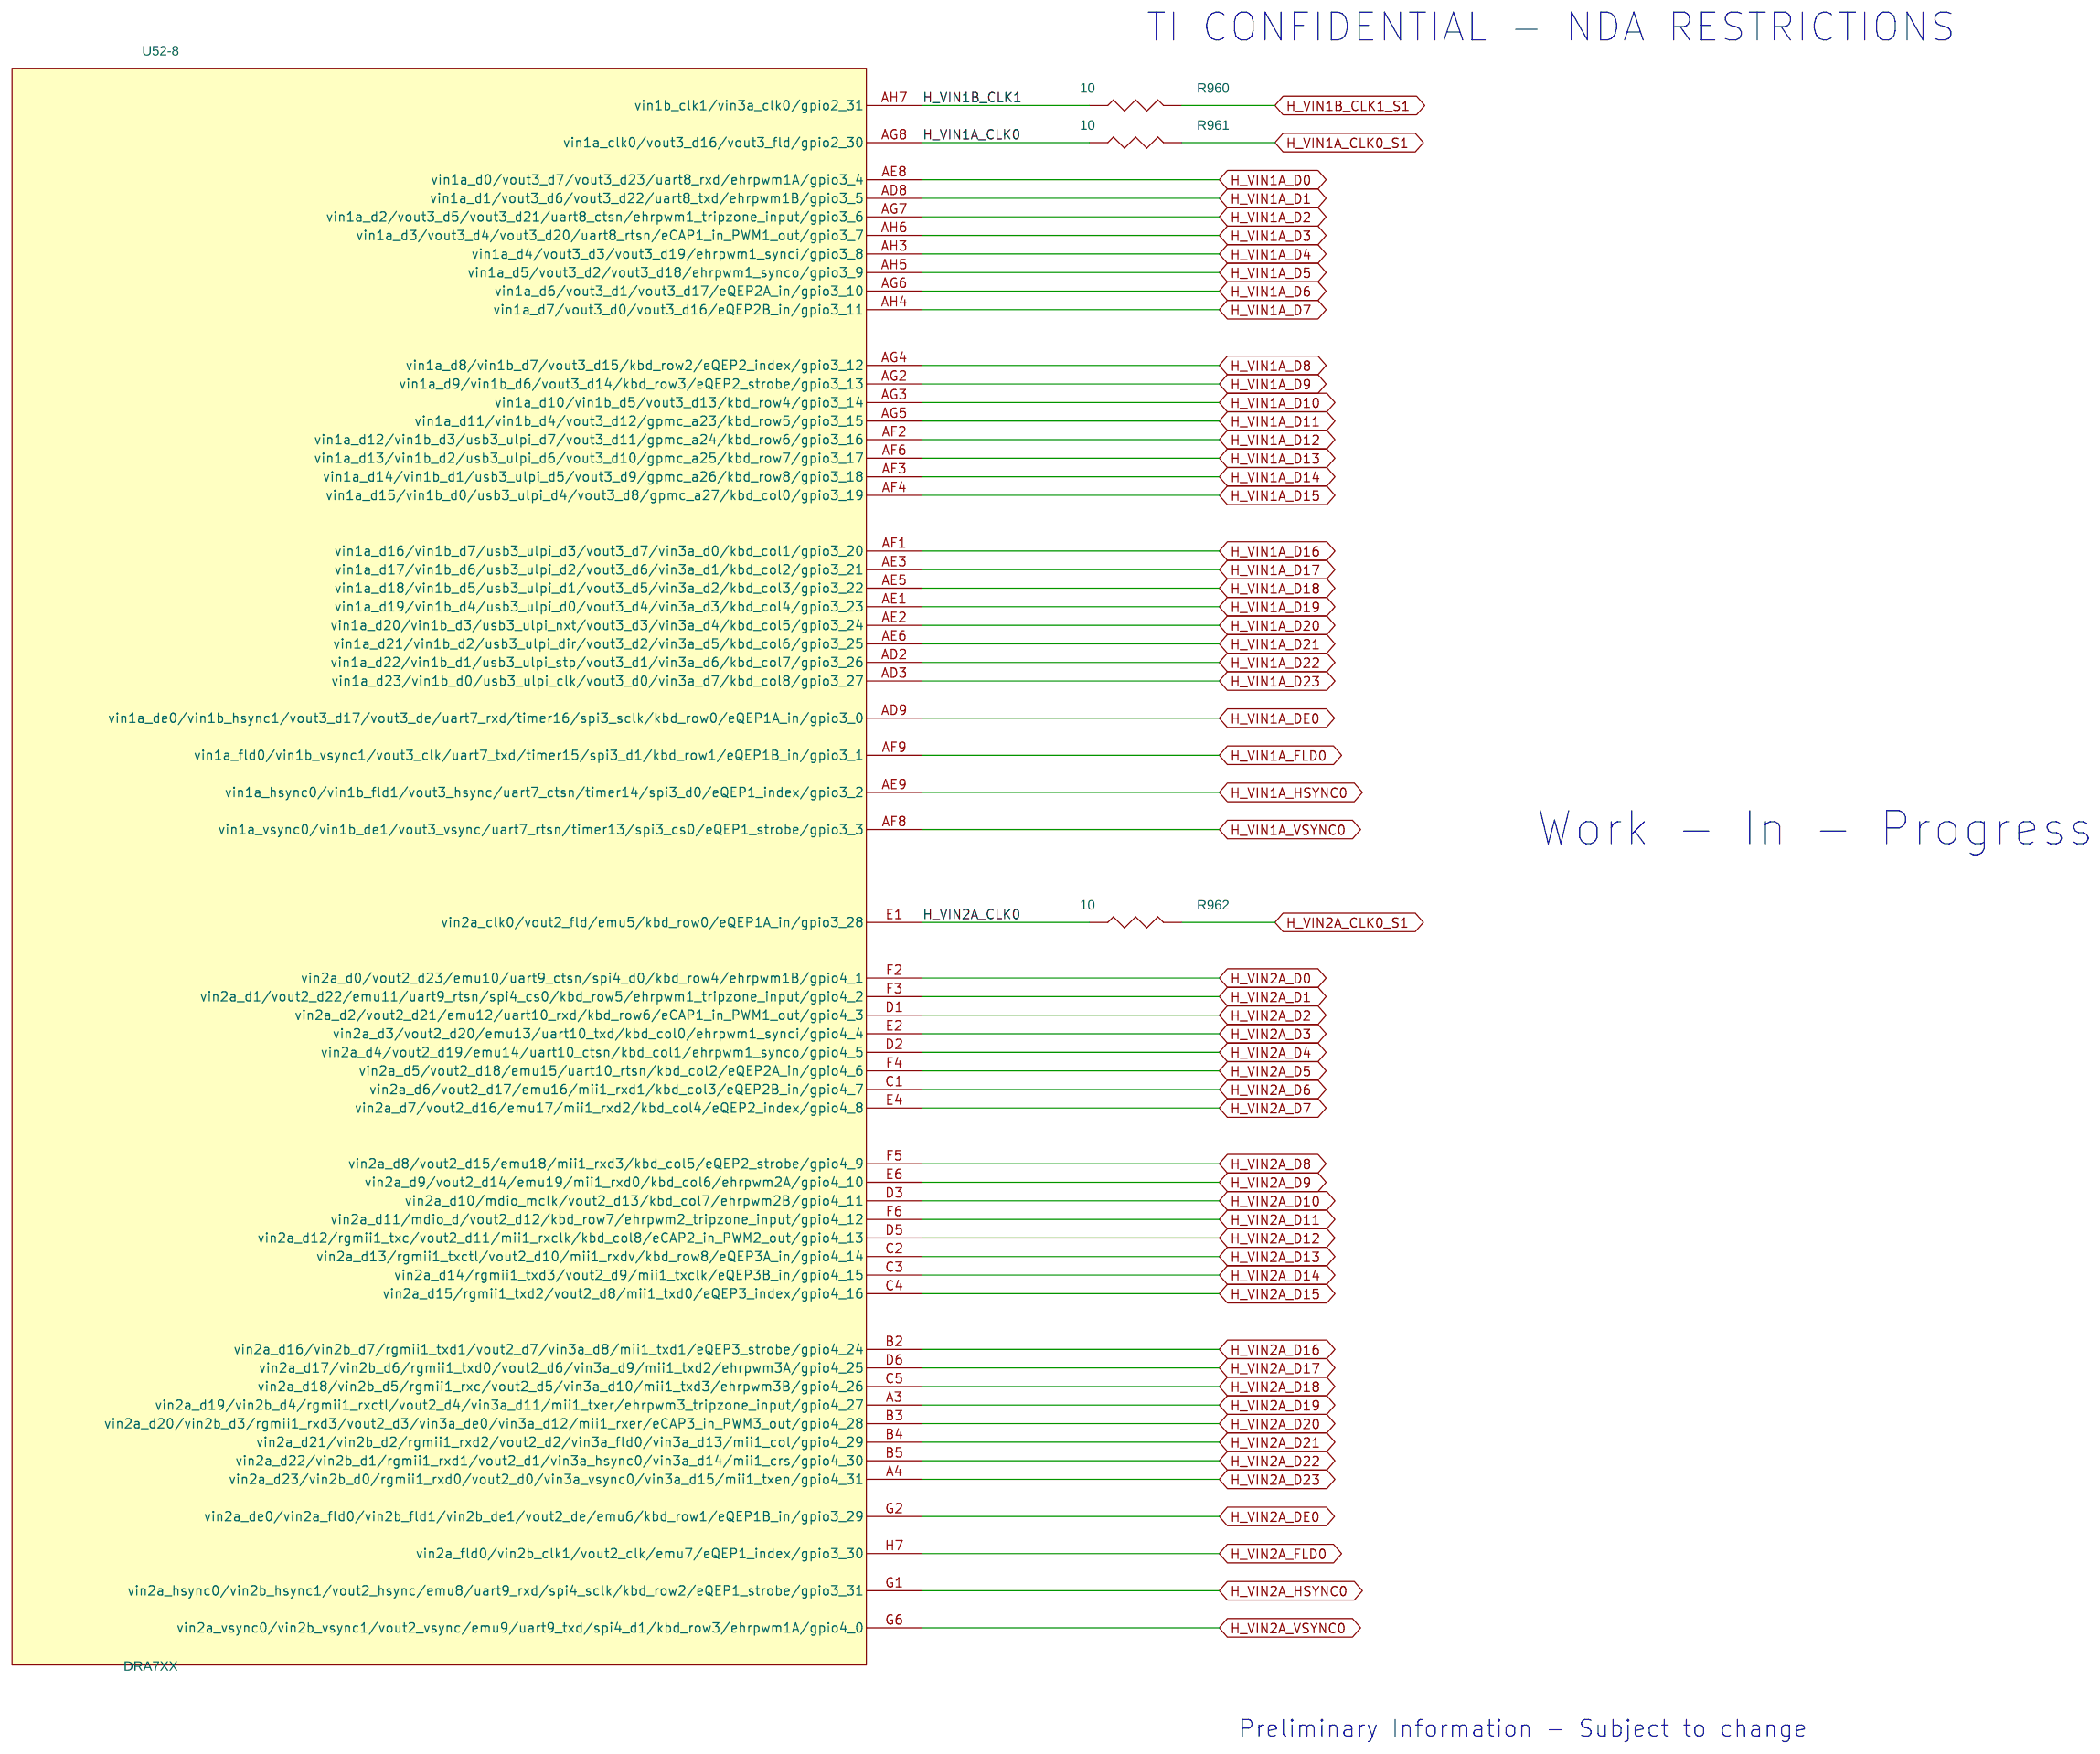
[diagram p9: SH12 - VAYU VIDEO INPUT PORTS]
11 SH13 - VAYU SATA PCIe: size B; rev: A
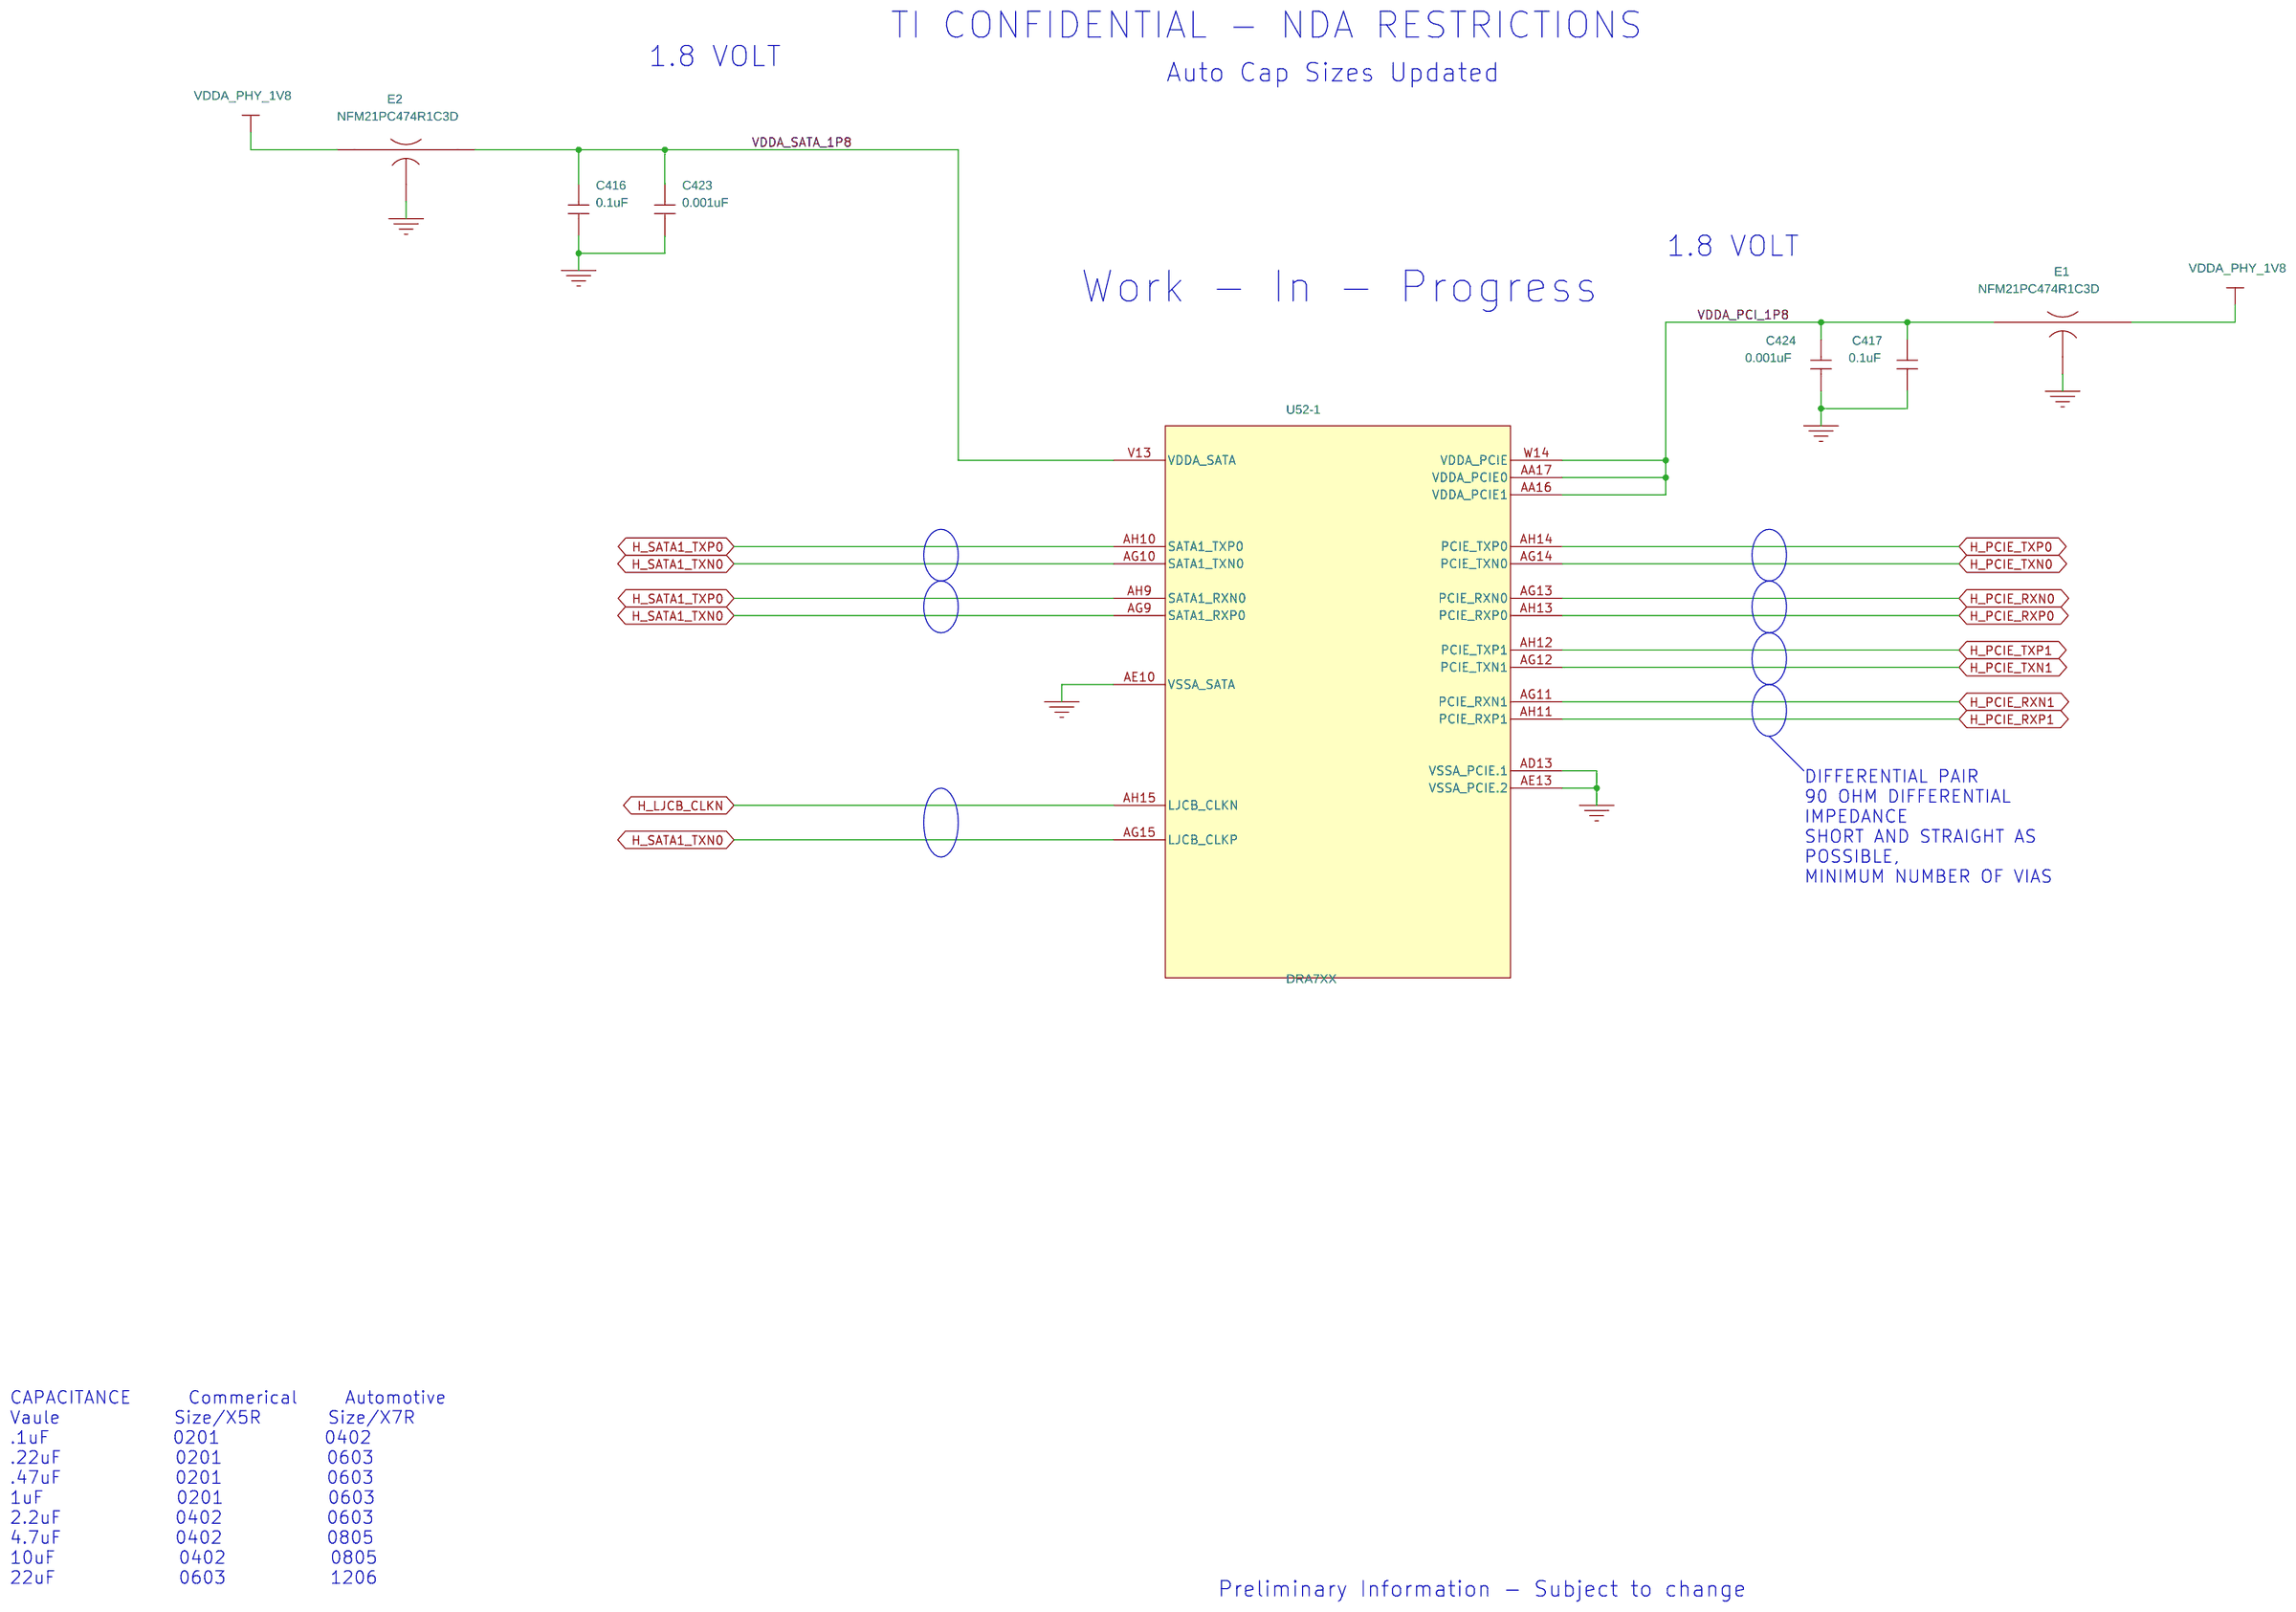
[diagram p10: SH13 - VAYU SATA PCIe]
12 SH14 - VAYU JTAG TRACE: size B; rev: A
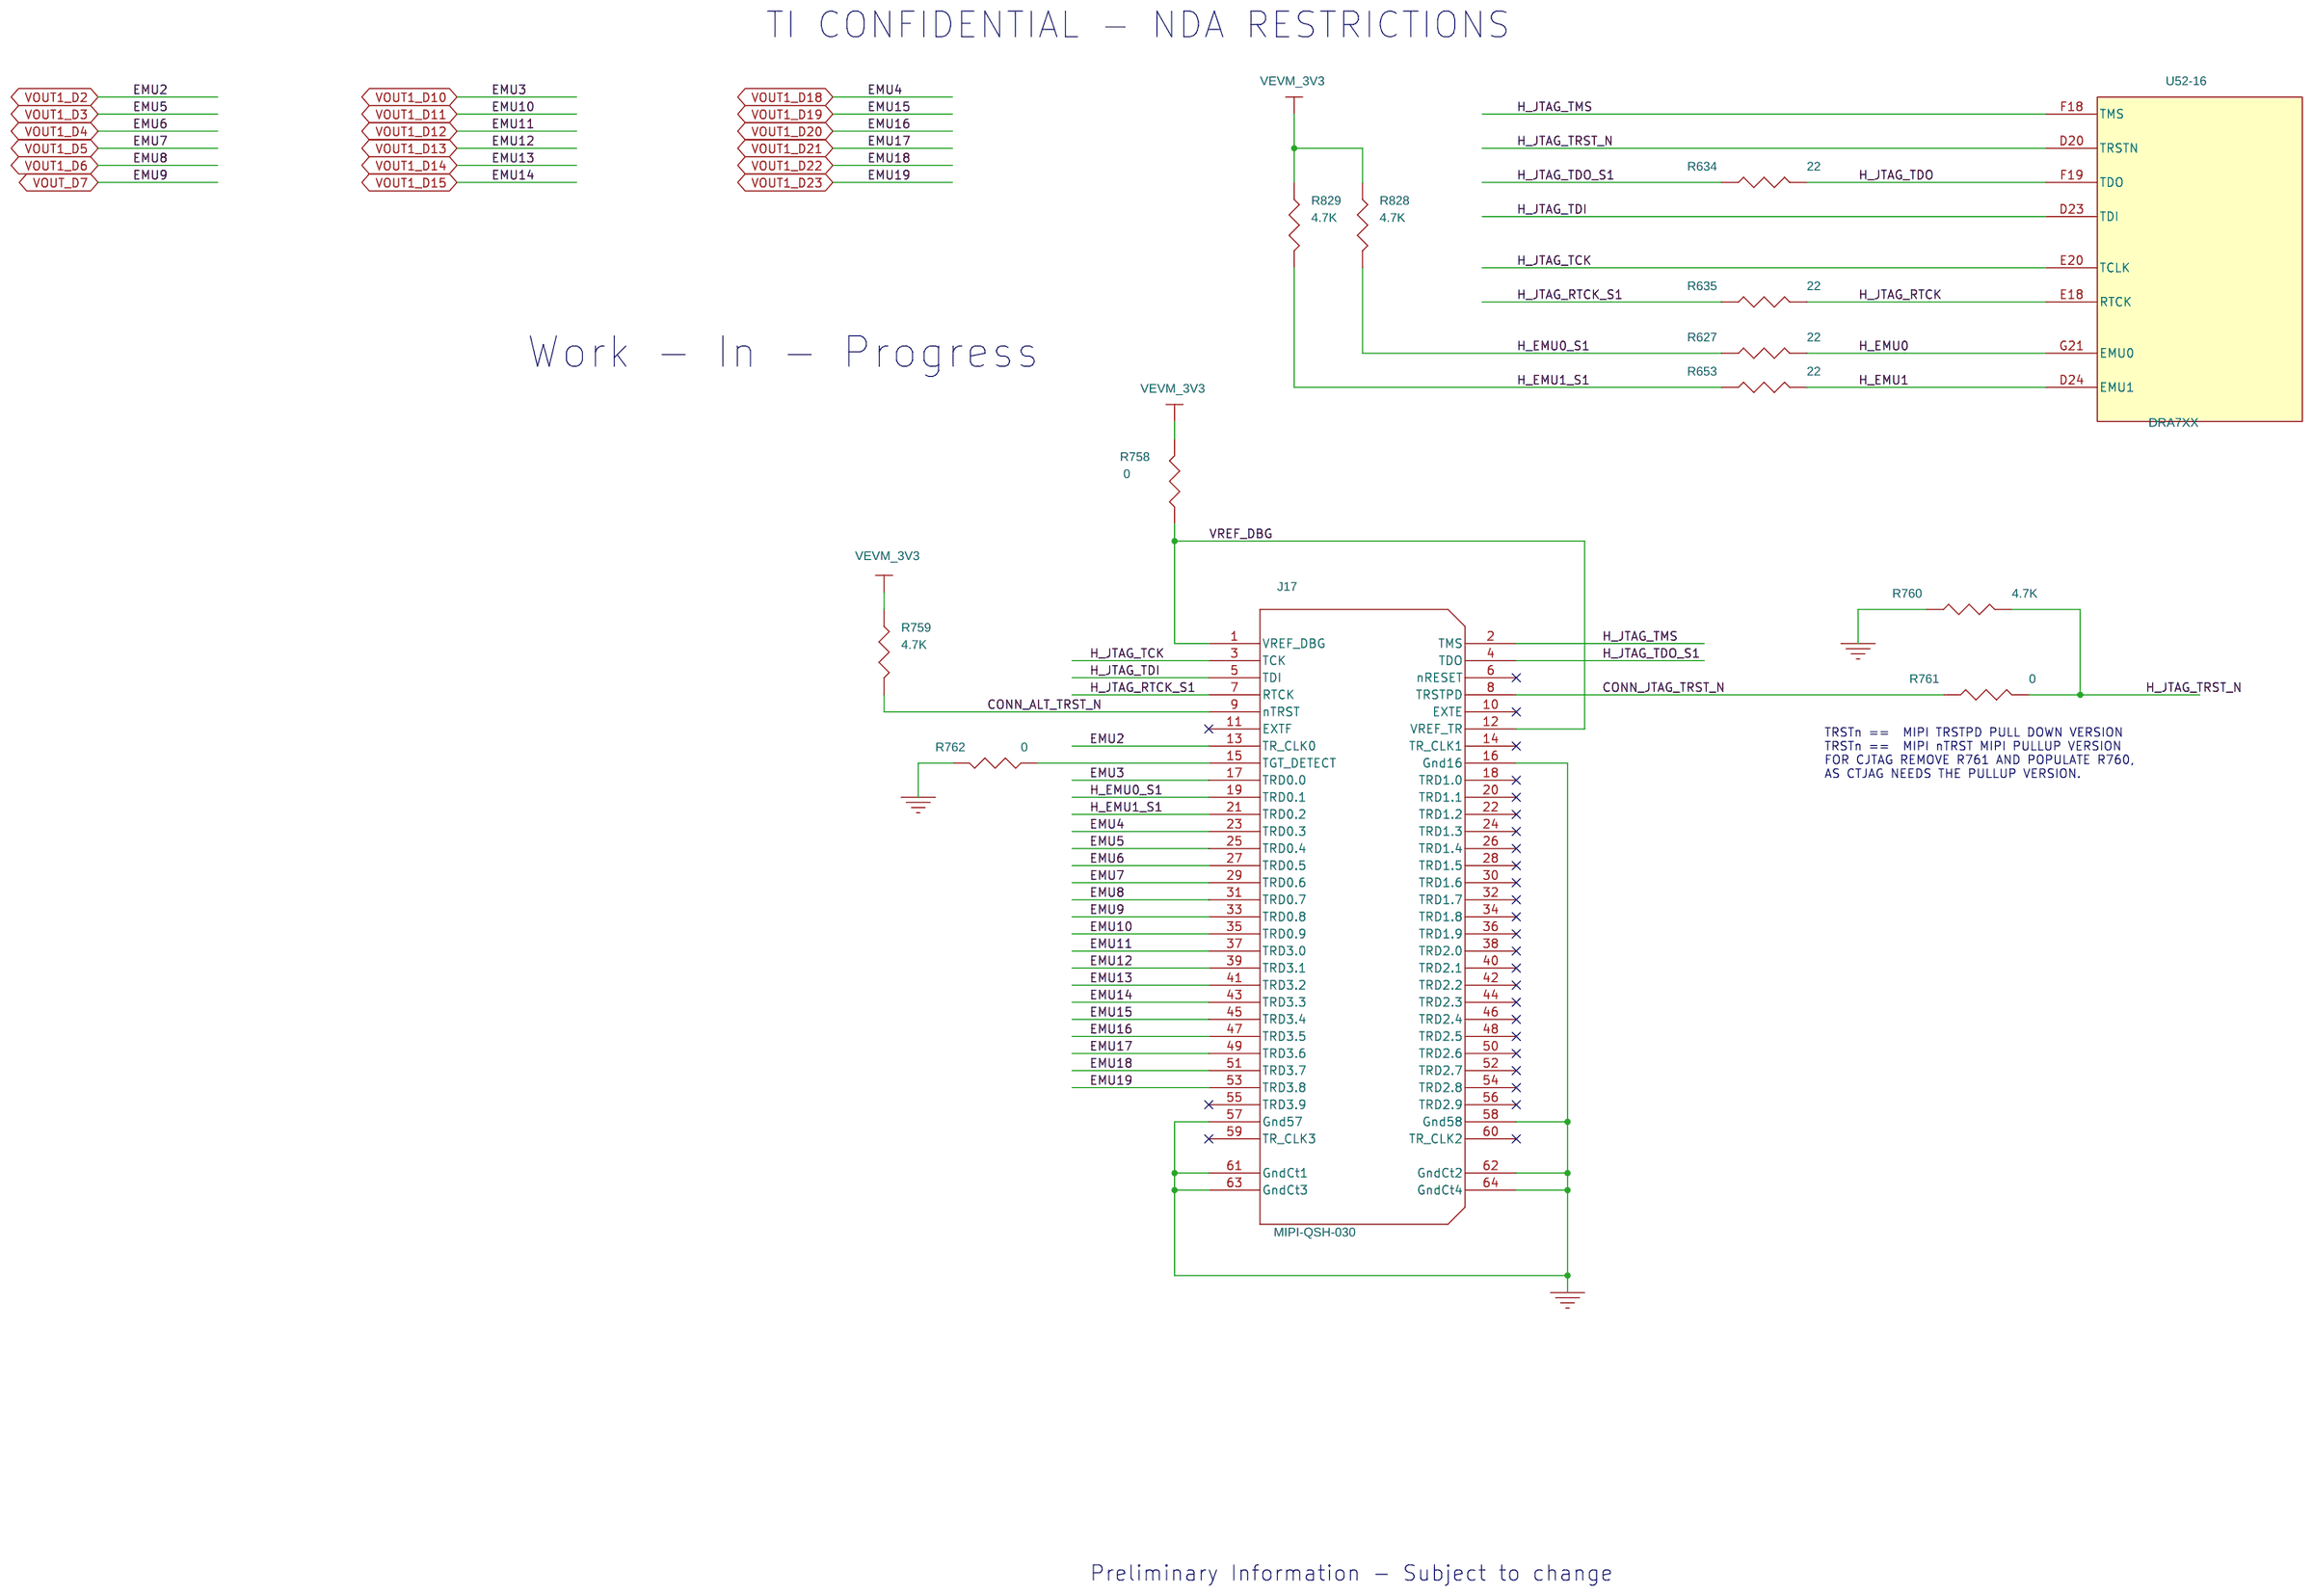
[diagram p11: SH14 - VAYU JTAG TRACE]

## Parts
sheet SH04 - VAYU SD MMC
C14  0.1uF  [c402-25]
C15  0.1uF  [c402-25]
C16  0.1uF  [c402-25]
C233  10uF  [c805-35x60]
C693  0.1uF  [c402-25]
C787  0.1uF  [c402-25]
P14  MicroSD_CARD  [molex-49225-201]
R14  10K  [r402-25]
R15  10K  [r402-25]
R16  10K  [r402-25]
R17  10K  [r402-25]
R18  10K  [r402-25]
R19  10K  [r402-25]
R327  10K  [r402-25]
R340  33  [r402-25]
R341  33  [r402-25]
R342  33  [r402-25]
R343  33  [r402-25]
R344  33  [r402-25]
R345  33  [r402-25]
R774  0  [r603-35x45]
R859  22  [r402-25]
R964  1K  [r402-25]
U77  TPD2E001DRL-Q1  [drl5-12x40]
U78  TPD2E001DRL-Q1  [drl5-12x40]
U79  TPD2E001DRL-Q1  [drl5-12x40]
U131  TPD2E001DRL-Q1  [drl5-12x40]
sheet SH05 - VAYU ETHERNET
R917  10  [r402-25]
R918  10  [r402-25]
R919  10  [r402-25]
R920  10  [r402-25]
R921  10  [r402-25]
R922  10  [r402-25]
R923  10  [r402-25]
R924  10  [r402-25]
R925  10  [r402-25]
R926  10  [r402-25]
R927  10  [r402-25]
R928  10  [r402-25]
R929  10  [r402-25]
R930  10  [r402-25]
R931  10  [r402-25]
U52  DRA7XX  [bga-zkk-6334-p760]  (sections -1,-10,-11,-12,-13,-14,-15,-16,-17,-18,-19,-2,-20,-21,-22,-23,-3,-4,-5,-6,-7,-8,-9)
sheet SH06 - VAYU USB
C439  0.001uF  [c402-25]
C440  10uF  [c805-35x60]
C451  0.01uF  [c402-25]
C486  0.1uF  [c402-25]
C489  0.1uF  [c402-25]
C510  0.01uF  [c402-25]
C511  0.001uF  [c402-25]
sheet SH07 - VAYU GPMC
R494  10  [r402-25]
R495  10  [r402-25]
R963  0  [r402-25]
RN30  RPACK4-10  [rpak8-10x25-28v]
RN31  RPACK4-10  [rpak8-10x25-28v]
sheet SH08 - VAYU DDR EMIF1
C514  0.1uF  [c402-25]
sheet SH09 - VAYU DDR EMIF2
C147  0.1uF  [c402-25]
sheet SH10 - VAYU HDMI MLB
C470  0.1uF  [c402-25]
C538  0.001uF  [c402-25]
C539  0.1uF  [c402-25]
E9  NFM21PC474R1C3D  [emi-NFM21p]
R182  100  [r402-25]
R183  100  [r402-25]
R184  100  [r402-25]
TP97  TESTPOINT  [tp1-18rd8]
TP98  TESTPOINT  [tp1-18rd8]
TP99  TESTPOINT  [tp1-18rd8]
TP100  TESTPOINT  [tp1-18rd8]
TP101  TESTPOINT  [tp1-18rd8]
TP102  TESTPOINT  [tp1-18rd8]
TP103  TESTPOINT  [tp1-18rd8]
TP104  TESTPOINT  [tp1-18rd8]
TP105  TESTPOINT  [tp1-18rd8]
TP106  TESTPOINT  [tp1-18rd8]
TP107  TESTPOINT  [tp1-18rd8]
TP108  TESTPOINT  [tp1-18rd8]
TP109  TESTPOINT  [tp1-18rd8]
TP110  TESTPOINT  [tp1-18rd8]
sheet SH12 - VAYU VIDEO INPUT PORTS
R960  10  [r402-25]
R961  10  [r402-25]
R962  10  [r402-25]
sheet SH13 - VAYU SATA PCIe
C416  0.1uF  [c402-25]
C417  0.1uF  [c402-25]
C423  0.001uF  [c402-25]
C424  0.001uF  [c402-25]
E1  NFM21PC474R1C3D  [emi-NFM21p]
E2  NFM21PC474R1C3D  [emi-NFM21p]
sheet SH14 - VAYU JTAG TRACE
J17  MIPI-QSH-030  [qsh-030-01-f]
R627  22  [r402-25]
R634  22  [r402-25]
R635  22  [r402-25]
R653  22  [r402-25]
R758  0  [r402-25]
R759  4.7K  [r402-25]
R760  4.7K  [r402-25]
R761  0  [r402-25]
R762  0  [r402-25]
R828  4.7K  [r402-25]
R829  4.7K  [r402-25]

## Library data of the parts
C14-C16 C693 C787 = Cap_100nF_Cermc_16V_10%_603_4: Part #: 101587-1100R
C233 = CAP: Part #: 102963-0101R
P14 = MM_CARD_0: Part #: 103053-0001R
R14-R19 R327 = RESISTOR: Part #: 101370-1003R
R340-R345 = RESISTOR: Part #: 101370-3300R
R774 = R: Part #: 100687-0001R
R627 R634 R635 R653 R859 = R: Part #: 101370-2200R
R964 = RESISTOR: Part #: 101370-1002R
U77-U79 U131 = TPDE0001RSE_0: Part #: 102728-0001R
R494 R495 R917-R931 R960-R963 = R: Part #: 103158-1000R
U52 = VAYU_DEC_3_2: Part #: 104183-0001R
C423 C424 C439 C511 C538 = CAP_NP: Part #: 103367-1102R
C440 = CAP_NP: Part #: 102963-0101R
C451 C510 = CAP_NP: Part #: 103241-1101R
C147 C416 C417 C470 C486 C489 C539 = CAP_NP: Part #: 103241-1100R
RN30 RN31 = R-PACK4: Part #: 101327-1000R
C514 = CAP: Part #: 103241-1100R
E1 E2 E9 = NFM_1: Part #: 102569-1470R
R182-R184 = R: Part #: 101370-1001R
TP97-TP110 = TESTPOINT
J17 = MIPI-QTH-030_1: Part #: 101884-0030R
R758 R761 R762 = R: Part #: 101370-0001R
R759 R760 R828 R829 = R: Part #: 101370-4702R

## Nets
GND: C14.2 C15.2 C16.2 C147.2 C233.2 C416.2 C417.2 C423.2 C424.2 C439.2 C440.2 C451.2 C470.2 C486.2 C489.2 C510.2 C511.2 C514.2 C538.2 C539.2 C693.2 C787.2 E1.2 E2.2 E9.2 J17.16(Gnd16) J17.57(Gnd57) J17.58(Gnd58) J17.61(GndCt1) J17.62(GndCt2) J17.63(GndCt3) J17.64(GndCt4) P14.6(VSS) R760.1 R762.1 R964.2 U52.AA11(VSSA_USB.2) U52.AB11(VSSA_USB.1) U52.AD10(VSSA_USB3) U52.AD13(VSSA_PCIE.1) U52.AD19(VSSA_HDMI.2) U52.AE10(VSSA_SATA) U52.AE13(VSSA_PCIE.2) U52.AE19(VSSA_HDMI.1) U77.4(GND) U78.4(GND) U79.4(GND) U131.4(GND) ; also on sheet 13 14 15 16 17 18 19 20 21 22 24 25 28 29 31 32 33 34 35 36 37 38 39 40 41 42 43 44 45 46 47 48 49 50 51 52 55 57
VDDA_HDMI: C538.1 C539.1 E9.1 U52.Y17(VDDA_HDMI)
VDDA_PCI_1P8: C417.1 C424.1 E1.1 U52.AA16(VDDA_PCIE1) U52.AA17(VDDA_PCIE0) U52.W14(VDDA_PCIE)
VDDA_PHY_1V8: C486.1 C510.1 C511.1 E1.3 E2.3 E9.3 U52.AA13(VDDA_USB1) U52.AB12(VDDA_USB2) U52.W12(VDDA_USB3) ; also on sheet 41
VDDA_SATA_1P8: C416.1 C423.1 E2.1 U52.V13(VDDA_SATA)
VDDR_VREFSTL: C147.1 C514.1 U52.N22(DDR2_VREF0) U52.Y18(DDR1_VREF0) ; also on sheet 24 28 50
VDDS_1V8: C470.1 U52.AA7(VDDS_MLBP.1) U52.Y7(VDDS_MLBP.2) ; also on sheet 16 43
CON_MMC1_CLK: P14.5(CLK) R17.2 R343.2 U78.3(IO1)
CON_MMC1_CMD: P14.3(CMD) R16.2 R344.2 U78.5(IO2)
CON_MMC1_DAT0: P14.7(DAT0) R18.2 R342.2 U77.5(IO2)
CON_MMC1_DAT1: P14.8(DAT1) R19.2 R341.2 U77.3(IO1)
CON_MMC1_DAT2: P14.1(DAT2) R14.2 R340.2 U79.5(IO2)
CON_MMC1_DAT3: P14.2(DAT3) R15.2 R345.2 U79.3(IO1)
CONN_ALT_TRST_N: J17.9(nTRST) R759.2
CONN_JTAG_TRST_N: J17.8(TRSTPD) R761.1
H_DDR1_A0: U52.AD20(DDR1_A0) ; also on sheet 23 24 26
H_DDR1_A1: U52.AC19(DDR1_A1) ; also on sheet 24 26
H_DDR1_A2: U52.AC20(DDR1_A2) ; also on sheet 24 26
H_DDR1_A3: U52.AB19(DDR1_A3) ; also on sheet 24 26
H_DDR1_A4: U52.AF21(DDR1_A4) ; also on sheet 24 26
H_DDR1_A5: U52.AH22(DDR1_A5) ; also on sheet 24 26
H_DDR1_A6: U52.AG23(DDR1_A6) ; also on sheet 24 26
H_DDR1_A7: U52.AE21(DDR1_A7) ; also on sheet 24 26
H_DDR1_A8: U52.AF22(DDR1_A8) ; also on sheet 24 26
H_DDR1_A9: U52.AE22(DDR1_A9) ; also on sheet 24 26
H_DDR1_A10: U52.AD21(DDR1_A10) ; also on sheet 24 26
H_DDR1_A11: U52.AD22(DDR1_A11) ; also on sheet 24 26
H_DDR1_A12: U52.AC21(DDR1_A12) ; also on sheet 24 26
H_DDR1_A13: U52.AF18(DDR1_A13) ; also on sheet 24 26
H_DDR1_A14: U52.AE17(DDR1_A14) ; also on sheet 24 26
H_DDR1_A15: U52.AD18(DDR1_A15) ; also on sheet 24 26
H_DDR1_BA0: U52.AF17(DDR1_BA0) ; also on sheet 24 26
H_DDR1_BA1: U52.AE18(DDR1_BA1) ; also on sheet 24 26
H_DDR1_BA2: U52.AB18(DDR1_BA2) ; also on sheet 24 26
H_DDR1_CASN: U52.AC18(DDR1_CASN) ; also on sheet 24 26
H_DDR1_CKE: U52.AG22(DDR1_CKE) ; also on sheet 23 24 26
H_DDR1_CLK0: U52.AG24(DDR1_CK) ; also on sheet 24 26
H_DDR1_CLK0N: U52.AH24(DDR1_NCK) ; also on sheet 24 26
H_DDR1_CSN0: U52.AH23(DDR1_CS0N) ; also on sheet 24 26
H_DDR1_D0: U52.AF25(DDR1_D0) ; also on sheet 24
H_DDR1_D1: U52.AF26(DDR1_D1) ; also on sheet 24
H_DDR1_D2: U52.AG26(DDR1_D2) ; also on sheet 24
H_DDR1_D3: U52.AH26(DDR1_D3) ; also on sheet 24
H_DDR1_D4: U52.AF24(DDR1_D4) ; also on sheet 24
H_DDR1_D5: U52.AE24(DDR1_D5) ; also on sheet 24
H_DDR1_D6: U52.AF23(DDR1_D6) ; also on sheet 24
H_DDR1_D7: U52.AE23(DDR1_D7) ; also on sheet 24
H_DDR1_D8: U52.AC23(DDR1_D8) ; also on sheet 24
H_DDR1_D9: U52.AF27(DDR1_D9) ; also on sheet 24
H_DDR1_D10: U52.AG27(DDR1_D10) ; also on sheet 24
H_DDR1_D11: U52.AF28(DDR1_D11) ; also on sheet 24
H_DDR1_D12: U52.AE26(DDR1_D12) ; also on sheet 24
H_DDR1_D13: U52.AC25(DDR1_D13) ; also on sheet 24
H_DDR1_D14: U52.AC24(DDR1_D14) ; also on sheet 24
H_DDR1_D15: U52.AD25(DDR1_D15) ; also on sheet 24
H_DDR1_D16: U52.V20(DDR1_D16) ; also on sheet 24
H_DDR1_D17: U52.W20(DDR1_D17) ; also on sheet 24
H_DDR1_D18: U52.AB28(DDR1_D18) ; also on sheet 24
H_DDR1_D19: U52.AC28(DDR1_D19) ; also on sheet 24
H_DDR1_D20: U52.AC27(DDR1_D20) ; also on sheet 24
H_DDR1_D21: U52.Y19(DDR1_D21) ; also on sheet 24
H_DDR1_D22: U52.AB27(DDR1_D22) ; also on sheet 24
H_DDR1_D23: U52.Y20(DDR1_D23) ; also on sheet 24
H_DDR1_D24: U52.AA23(DDR1_D24) ; also on sheet 24
H_DDR1_D25: U52.Y22(DDR1_D25) ; also on sheet 24
H_DDR1_D26: U52.Y23(DDR1_D26) ; also on sheet 24
H_DDR1_D27: U52.AA24(DDR1_D27) ; also on sheet 24
H_DDR1_D28: U52.Y24(DDR1_D28) ; also on sheet 24
H_DDR1_D29: U52.AA26(DDR1_D29) ; also on sheet 24
H_DDR1_D30: U52.AA25(DDR1_D30) ; also on sheet 24
H_DDR1_D31: U52.AA28(DDR1_D31) ; also on sheet 24
H_DDR1_DQM0: U52.AD23(DDR1_DQM0) ; also on sheet 24
H_DDR1_DQM1: U52.AB23(DDR1_DQM1) ; also on sheet 24
H_DDR1_DQM2: U52.AC26(DDR1_DQM2) ; also on sheet 24
H_DDR1_DQM3: U52.AA27(DDR1_DQM3) ; also on sheet 24
H_DDR1_DQM_ECC: U52.V26(DDR1_DQM_ECC) ; also on sheet 24
H_DDR1_DQS0: U52.AH25(DDR1_DQS0) ; also on sheet 24
H_DDR1_DQS1: U52.AE27(DDR1_DQS1) ; also on sheet 24
H_DDR1_DQS2: U52.AD27(DDR1_DQS2) ; also on sheet 24
H_DDR1_DQS3: U52.Y28(DDR1_DQS3) ; also on sheet 24
H_DDR1_DQS_ECC: U52.V27(DDR1_DQS_ECC) ; also on sheet 24
H_DDR1_DQSN0: U52.AG25(DDR1_DQSN0) ; also on sheet 24
H_DDR1_DQSN1: U52.AE28(DDR1_DQSN1) ; also on sheet 24
H_DDR1_DQSN2: U52.AD28(DDR1_DQSN2) ; also on sheet 24
H_DDR1_DQSN3: U52.Y27(DDR1_DQSN3) ; also on sheet 24
H_DDR1_DQSN_ECC: U52.V28(DDR1_DQSN_ECC) ; also on sheet 24
H_DDR1_ECC_D0: U52.W22(DDR1_ECC_D0) ; also on sheet 24
H_DDR1_ECC_D1: U52.V23(DDR1_ECC_D1) ; also on sheet 24
H_DDR1_ECC_D2: U52.W19(DDR1_ECC_D2) ; also on sheet 24
H_DDR1_ECC_D3: U52.W23(DDR1_ECC_D3) ; also on sheet 24
H_DDR1_ECC_D4: U52.Y25(DDR1_ECC_D4) ; also on sheet 24
H_DDR1_ECC_D5: U52.V24(DDR1_ECC_D5) ; also on sheet 24
H_DDR1_ECC_D6: U52.V25(DDR1_ECC_D6) ; also on sheet 24
H_DDR1_ECC_D7: U52.Y26(DDR1_ECC_D7) ; also on sheet 24
H_DDR1_ODT0: U52.AE20(DDR1_ODT0) ; also on sheet 24 26
H_DDR1_RASN: U52.AF20(DDR1_RASN) ; also on sheet 24 26
H_DDR1_RST: U52.AG21(DDR1_RST) ; also on sheet 24
H_DDR1_WEN: U52.AH21(DDR1_WEN) ; also on sheet 24 26
H_DDR2_A0: U52.R25(DDR2_A0) ; also on sheet 27 28 30
H_DDR2_A1: U52.R26(DDR2_A1) ; also on sheet 27 28 30
H_DDR2_A2: U52.R28(DDR2_A2) ; also on sheet 27 28 30
H_DDR2_A3: U52.R27(DDR2_A3) ; also on sheet 27 28 30
H_DDR2_A4: U52.P23(DDR2_A4) ; also on sheet 27 28 30
H_DDR2_A5: U52.P22(DDR2_A5) ; also on sheet 27 28 30
H_DDR2_A6: U52.P25(DDR2_A6) ; also on sheet 27 28 30
H_DDR2_A7: U52.N20(DDR2_A7) ; also on sheet 27 28 30
H_DDR2_A8: U52.P27(DDR2_A8) ; also on sheet 27 28 30
H_DDR2_A9: U52.N27(DDR2_A9) ; also on sheet 27 28 30
H_DDR2_A10: U52.N23(DDR2_A10) ; also on sheet 27 28 30
H_DDR2_A11: U52.P26(DDR2_A11) ; also on sheet 27 28 30
H_DDR2_A12: U52.N28(DDR2_A12) ; also on sheet 27 28 30
H_DDR2_A13: U52.T22(DDR2_A13) ; also on sheet 27 28 30
H_DDR2_A14: U52.R22(DDR2_A14) ; also on sheet 27 28 30
H_DDR2_A15: U52.U22(DDR2_A15) ; also on sheet 27 28 30
H_DDR2_BA0: U52.U23(DDR2_BA0) ; also on sheet 27 28 30
H_DDR2_BA1: U52.U27(DDR2_BA1) ; also on sheet 27 28 30
H_DDR2_BA2: U52.U26(DDR2_BA2) ; also on sheet 27 28 30
H_DDR2_CASN: U52.U28(DDR2_CASN) ; also on sheet 27 28 30
H_DDR2_CKE: U52.U24(DDR2_CKE) ; also on sheet 27 28 30
H_DDR2_CLK0: U52.T28(DDR2_CK) ; also on sheet 27 28 30
H_DDR2_CLK0N: U52.T27(DDR2_NCK) ; also on sheet 27 28 30
H_DDR2_CSN0: U52.P24(DDR2_CSN0) ; also on sheet 27 28 30
H_DDR2_D0: U52.E26(DDR2_D0) ; also on sheet 28
H_DDR2_D1: U52.G25(DDR2_D1) ; also on sheet 28
H_DDR2_D2: U52.F25(DDR2_D2) ; also on sheet 28
H_DDR2_D3: U52.F24(DDR2_D3) ; also on sheet 28
H_DDR2_D4: U52.F26(DDR2_D4) ; also on sheet 28
H_DDR2_D5: U52.F27(DDR2_D5) ; also on sheet 28
H_DDR2_D6: U52.E27(DDR2_D6) ; also on sheet 28
H_DDR2_D7: U52.E28(DDR2_D7) ; also on sheet 28
H_DDR2_D8: U52.H23(DDR2_D8) ; also on sheet 28
H_DDR2_D9: U52.H25(DDR2_D9) ; also on sheet 28
H_DDR2_D10: U52.H24(DDR2_D10) ; also on sheet 28
H_DDR2_D11: U52.H26(DDR2_D11) ; also on sheet 28
H_DDR2_D12: U52.G26(DDR2_D12) ; also on sheet 28
H_DDR2_D13: U52.J25(DDR2_D13) ; also on sheet 28
H_DDR2_D14: U52.J26(DDR2_D14) ; also on sheet 28
H_DDR2_D15: U52.J24(DDR2_D15) ; also on sheet 28
H_DDR2_D16: U52.L22(DDR2_D16) ; also on sheet 28
H_DDR2_D17: U52.K20(DDR2_D17) ; also on sheet 28
H_DDR2_D18: U52.K21(DDR2_D18) ; also on sheet 28
H_DDR2_D19: U52.L23(DDR2_D19) ; also on sheet 28
H_DDR2_D20: U52.L24(DDR2_D20) ; also on sheet 28
H_DDR2_D21: U52.J23(DDR2_D21) ; also on sheet 28
H_DDR2_D22: U52.K22(DDR2_D22) ; also on sheet 28
H_DDR2_D23: U52.J20(DDR2_D23) ; also on sheet 28
H_DDR2_D24: U52.L27(DDR2_D24) ; also on sheet 28
H_DDR2_D25: U52.L26(DDR2_D25) ; also on sheet 28
H_DDR2_D26: U52.L25(DDR2_D26) ; also on sheet 28
H_DDR2_D27: U52.L28(DDR2_D27) ; also on sheet 28
H_DDR2_D28: U52.M23(DDR2_D28) ; also on sheet 28
H_DDR2_D29: U52.M24(DDR2_D29) ; also on sheet 28
H_DDR2_D30: U52.M25(DDR2_D30) ; also on sheet 28
H_DDR2_D31: U52.M26(DDR2_D31) ; also on sheet 28
H_DDR2_DQM0: U52.F28(DDR2_DQM0) ; also on sheet 28
H_DDR2_DQM1: U52.G24(DDR2_DQM1) ; also on sheet 28
H_DDR2_DQM2: U52.K23(DDR2_DQM2) ; also on sheet 28
H_DDR2_DQM3: U52.M22(DDR2_DQM3) ; also on sheet 28
H_DDR2_DQS0: U52.G28(DDR2_DQS0) ; also on sheet 28
H_DDR2_DQS1: U52.H27(DDR2_DQS1) ; also on sheet 28
H_DDR2_DQS2: U52.K27(DDR2_DQS2) ; also on sheet 28
H_DDR2_DQS3: U52.M28(DDR2_DQS3) ; also on sheet 28
H_DDR2_DQSN0: U52.G27(DDR2_DQSn0) ; also on sheet 28
H_DDR2_DQSN1: U52.H28(DDR2_DQSN1) ; also on sheet 28
H_DDR2_DQSN2: U52.K28(DDR2_DQSN2) ; also on sheet 28
H_DDR2_DQSN3: U52.M27(DDR2_DQSN3) ; also on sheet 28
H_DDR2_ODT0: U52.R23(DDR2_ODT0) ; also on sheet 27 28 30
H_DDR2_RASN: U52.T23(DDR2_RASN) ; also on sheet 27 28 30
H_DDR2_RST: U52.R24(DDR2_RST) ; also on sheet 28
H_DDR2_WEN: U52.U25(DDR2_WEN) ; also on sheet 27 28 30
H_EMU0: R627.2 U52.G21(EMU0)
H_EMU0_S1: J17.19(TRD0.1) R627.1 R828.2
H_EMU1: R653.2 U52.D24(EMU1)
H_EMU1_S1: J17.21(TRD0.2) R653.1 R829.2
H_GPIO6_28: U52.Y9(mmc1_sdwp/uart6_txd/i2c4_scl/gpio6_28)
H_GPMC_A0: U52.R6(gpmc_a0/vin3a_d16/vout3_d16/vin4a_d0/vin4b_d0/i2c4_scl/uart5_rxd/gpio7_3)
H_GPMC_A1: U52.T9(gpmc_a1/vin3a_d17/vout3_d17/vin4a_d1/vin4b_d1/i2c4_sda/uart5_txd/gpio7_4)
H_GPMC_A2: U52.T6(gpmc_a2/vin3a_d18/vout3_d18/vin4a_d2/vin4b_d2/uart7_rxd/uart5_ctsn/gpio7_5)
H_GPMC_A3: U52.T7(gpmc_a3/qspi1_cs2/vin3a_d19/vout3_d19/vin4a_d3/vin4b_d3/uart7_txd/uart5_rtsn/gpio7_6)
H_GPMC_A4: U52.P6(gpmc_a4/qspi1_cs3/vin3a_d20/vout3_d20/vin4a_d4/vin4b_d4/i2c5_scl/uart6_rxd/gpio1_26)
H_GPMC_A5: U52.R9(gpmc_a5/vin3a_d21/vout3_d21/vin4a_d5/vin4b_d5/i2c5_sda/uart6_txd/gpio1_27)
H_GPMC_A6: U52.R5(gpmc_a6/vin3a_d22/vout3_d22/vin4a_d6/vin4b_d6/uart8_rxd/uart6_ctsn/gpio1_28)
H_GPMC_A7: U52.P5(gpmc_a7/vin3a_d23/vout3_d23/vin4a_d7/vin4b_d7/uart8_txd/uart6_rtsn/gpio1_29)
H_GPMC_A8: U52.N7(gpmc_a8/vin3a_hsync0/vout3_hsync/vin4b_hsync1/timer12/spi4_sclk/gpio1_30)
H_GPMC_A9: U52.R4(gpmc_a9/vin3a_vsync0/vout3_vsync/vin4b_vsync1/timer11/spi4_d1/gpio1_31)
H_GPMC_A10: U52.N9(gpmc_a10/vin3a_de0/vout3_de/vin4b_clk1/timer10/spi4_d0/gpio2_0)
H_GPMC_A11: U52.P9(gpmc_a11/vin3a_fld0/vout3_fld/vin4a_fld0/vin4b_de1/timer9/spi4_cs0/gpio2_1)
H_GPMC_A12: U52.P4(gpmc_a12/vin4a_clk0/gpmc_a0/vin4b_fld1/timer8/spi4_cs1/dma_evt1/gpio2_2)
H_GPMC_ADV_N: U52.N1(gpmc_advn_ale/gpmc_cs6/clkout2/gpmc_wait1/vin4a_vsync0/gpmc_a2/gpmc_a23/timer3/i2c3_sda/dma_evt2/gpio2_23)
H_GPMC_BEN0: U52.N6(gpmc_ben0/gpmc_cs4/vin1b_hsync1/vin3b_de1/timer2/dma_evt3/gpio2_26)
H_GPMC_BEN1: U52.M4(gpmc_ben1/gpmc_cs5/vin1b_de1/vin3b_clk1/gpmc_a3/vin3b_fld1/timer1/dma_evt4/gpio2_27)
H_GPMC_CLK: R494.2 U52.P7(gpmc_clk/gpmc_cs7/clkout1/gpmc_wait1/vin4a_hsync0/vin4a_de0/vin3b_clk1/timer4/i2c3_scl/dma_evt1/gpio2_22)
H_GPMC_CLK_S1: R494.1
H_GPMC_CS0_N: U52.T1(gpmc_cs0/gpio2_19)
H_GPMC_CS1_N: U52.H6(gpmc_cs1/mmc2_cmd/gpmc_a22/vin4a_de0/vin3b_vsync1/gpio2_18)
H_GPMC_CS2_N: U52.P2(gpmc_cs2/qspi1_cs0/gpio2_20)
H_GPMC_CS3_N: U52.P1(gpmc_cs3/qspi1_cs1/vin3a_clk0/vout3_clk/gpmc_a1/gpio2_21)
H_GPMC_D00: U52.M6(gpmc_ad0/vin3a_d0/vout3_d0/gpio1_6/sysboot0)
H_GPMC_D01: U52.M2(gpmc_ad1/vin3a_d1/vout3_d1/gpio1_7/sysboot1)
H_GPMC_D02: U52.L5(gpmc_ad2/vin3a_d2/vout3_d2/gpio1_8/sysboot2)
H_GPMC_D03: U52.M1(gpmc_ad3/vin3a_d3/vout3_d3/gpio1_9/sysboot3)
H_GPMC_D04: U52.L6(gpmc_ad4/vin3a_d4/vout3_d4/gpio1_10/sysboot4)
H_GPMC_D05: U52.L4(gpmc_ad5/vin3a_d5/vout3_d5/gpio1_11/sysboot5)
H_GPMC_D06: U52.L3(gpmc_ad6/vin3a_d6/vout3_d6/gpio1_12/sysboot6)
H_GPMC_D07: U52.L2(gpmc_ad7/vin3a_d7/vout3_d7/gpio1_13/sysboot7)
H_GPMC_D08: U52.L1(gpmc_ad8/vin3a_d8/vout3_d8/gpio7_18/sysboot8)
H_GPMC_D09: U52.K2(gpmc_ad9/vin3a_d9/vout3_d9/gpio7_19/sysboot9)
H_GPMC_D10: U52.J1(gpmc_ad10/vin3a_d10/vout3_d10/gpio7_28/sysboot10)
H_GPMC_D11: U52.J2(gpmc_ad11/vin3a_d11/vout3_d11/gpio7_29/sysboot11)
H_GPMC_D12: U52.H1(gpmc_ad12/vin3a_d12/vout3_d12/gpio1_18/sysboot12)
H_GPMC_D13: U52.J3(gpmc_ad13/vin3a_d13/vout3_d13/gpio1_19/sysboot13)
H_GPMC_D14: U52.H2(gpmc_ad14/vin3a_d14/vout3_d14/gpio1_20/sysboot14)
H_GPMC_D15: U52.H3(gpmc_ad15/vin3a_d15/vout3_d15/gpio1_21/sysboot15)
H_GPMC_OE_N: U52.M5(gpmc_oen_ren/gpio2_24)
H_GPMC_WAIT0: U52.N2(gpmc_wait0/gpio2_28)
H_GPMC_WE_N: U52.M3(gpmc_wen/gpio2_25)
H_HDMI_TX0+: TP98.1(TP) U52.AH17(HDMI1_DATA0Y)
H_HDMI_TX0-: TP97.1(TP) U52.AG17(HDMI1_DATA0X)
H_HDMI_TX1+: TP99.1(TP) U52.AH18(HDMI1_DATA1Y)
H_HDMI_TX1-: TP100.1(TP) U52.AG18(HDMI1_DATA1X)
H_HDMI_TX2+: TP101.1(TP) U52.AH19(HDMI1_DATA2Y)
H_HDMI_TX2-: TP102.1(TP) U52.AG19(HDMI1_DATA2X)
H_HDMI_TXC+: TP103.1(TP) U52.AH16(HDMI1_CLOCKY)
H_HDMI_TXC-: TP104.1(TP) U52.AG16(HDMI1_CLOCKX)
H_JTAG_RTCK: R635.2 U52.E18(RTCK)
H_JTAG_RTCK_S1: J17.7(RTCK) R635.1
H_JTAG_TCK: J17.3(TCK) U52.E20(TCLK)
H_JTAG_TDI: J17.5(TDI) U52.D23(TDI)
H_JTAG_TDO: R634.2 U52.F19(TDO)
H_JTAG_TDO_S1: J17.4(TDO) R634.1
H_JTAG_TMS: J17.2(TMS) U52.F18(TMS)
H_JTAG_TRST_N: R760.2 R761.2 U52.D20(TRSTN)
H_LJCB_CLKN: U52.AH15(LJCB_CLKN)
H_MCASP1_ACLKR: U52.B14(mcasp1_aclkr/mcasp7_axr2/vout2_d0/vin4a_d0/i2c4_sda/gpio5_0)
H_MCASP1_ACLKX: U52.C14(mcasp1_aclkx/vin6a_fld0/i2c3_sda/gpio7_31)
H_MCASP1_AXR0: U52.G12(mcasp1_axr0/uart6_rxd/vin6a_vsync0/i2c5_sda/gpio5_2)
H_MCASP1_AXR1: U52.F12(mcasp1_axr1/uart6_txd/vin6a_hsync0/i2c5_scl/gpio5_3)
H_MCASP1_AXR2: U52.G13(mcasp1_axr2/mcasp6_axr2/uart6_ctsn/vout2_d2/vin4a_d2/gpio5_4)
H_MCASP1_AXR3: U52.J11(mcasp1_axr3/mcasp6_axr3/uart6_rtsn/vout2_d3/vin4a_d3/gpio5_5)
H_MCASP1_AXR4: U52.E12(mcasp1_axr4/mcasp4_axr2/vout2_d4/vin4a_d4/gpio5_6)
H_MCASP1_AXR5: U52.F13(mcasp1_axr5/mcasp4_axr3/vout2_d5/vin4a_d5/gpio5_7)
H_MCASP1_AXR6: U52.C12(mcasp1_axr6/mcasp5_axr2/vout2_d6/vin4a_d6/gpio5_8)
H_MCASP1_AXR7: U52.D12(mcasp1_axr7/mcasp5_axr3/vout2_d7/vin4a_d7/timer4/gpio5_9)
H_MCASP1_AXR8: U52.B12(mcasp1_axr8/mcasp6_axr0/spi3_sclk/vin6a_d15/timer5/gpio5_10)
H_MCASP1_AXR9: U52.A11(mcasp1_axr9/mcasp6_axr1/spi3_d1/vin6a_d14/timer6/gpio5_11)
H_MCASP1_AXR10: U52.B13(mcasp1_axr10/mcasp6_aclkx/mcasp6_aclkr/spi3_d0/vin6a_d13/timer7/gpio5_12)
H_MCASP1_AXR11: U52.A12(mcasp1_axr11/mcasp6_fsx/mcasp6_fsr/spi3_cs0/vin6a_d12/timer8/gpio4_17)
H_MCASP1_AXR12: U52.E14(mcasp1_axr12/mcasp7_axr0/spi3_cs1/vin6a_d11/timer9/gpio4_18)
H_MCASP1_AXR13: U52.A13(mcasp1_axr13/mcasp7_axr1/vin6a_d10/timer10/gpio6_4)
H_MCASP1_AXR14: U52.G14(mcasp1_axr14/mcasp7_aclkx/mcasp7_aclkr/vin6a_d9/timer11/gpio6_5)
H_MCASP1_AXR15: U52.F14(mcasp1_axr15/mcasp7_fsx/mcasp7_fsr/vin6a_d8/timer12/gpio6_6)
H_MCASP1_FSR: U52.J14(mcasp1_fsr/mcasp7_axr3/vout2_d1/vin4a_d1/i2c4_scl/gpio5_1)
H_MCASP1_FSX: U52.D14(mcasp1_fsx/vin6a_de0/i2c3_scl/gpio7_30)
H_MCASP2_ACLKR: U52.E15(mcasp2_aclkr/mcasp8_axr2/vout2_d8/vin4a_d8)
H_MCASP2_ACLKX: U52.A19(mcasp2_aclkx/vin6a_d7)
H_MCASP2_AXR0: U52.B15(mcasp2_axr0/vout2_d10/vin4a_d10)
H_MCASP2_AXR1: U52.A15(mcasp2_axr1/vout2_d11/vin4a_d11)
H_MCASP2_AXR2: U52.C15(mcasp2_axr2/mcasp3_axr2/vin6a_d5/gpio6_8)
H_MCASP2_AXR3: U52.A16(mcasp2_axr3/mcasp3_axr3/vin6a_d4/gpio6_9)
H_MCASP2_AXR4: U52.D15(mcasp2_axr4/mcasp8_axr0/vout2_d12/vin4a_d12/gpio1_4)
H_MCASP2_AXR5: U52.B16(mcasp2_axr5/mcasp8_axr1/vout2_d13/vin4a_d13/gpio6_7)
H_MCASP2_AXR6: U52.B17(mcasp2_axr6/mcasp8_aclkx/mcasp8_aclkr/vout2_d14/vin4a_d14/gpio2_29)
H_MCASP2_AXR7: U52.A17(mcasp2_axr7/mcasp8_fsx/mcasp8_fsr/vout2_d15/vin4a_d15/gpio1_5)
H_MCASP2_FSR: U52.A20(mcasp2_fsr/mcasp8_axr3/vout2_d9/vin4a_d9)
H_MCASP2_FSX: U52.A18(mcasp2_fsx/vin6a_d6)
H_MCASP3_ACLKX: U52.B18(mcasp3_aclkx/mcasp3_aclkr/mcasp2_axr12/uart7_rxd/vin6a_d3/gpio5_13)
H_MCASP3_AFSX: U52.F15(mcasp3_fsx/mcasp3_fsr/mcasp2_axr13/uart7_txd/vin6a_d2/gpio5_14)
H_MCASP3_AXR0: U52.B19(mcasp3_axr0/mcasp2_axr14/uart7_ctsn/uart5_rxd/vin6a_d1)
H_MCASP3_AXR1: U52.C17(mcasp3_axr1/mcasp2_axr15/uart7_rtsn/uart5_txd/vin6a_d0/vin5a_fld0)
H_MCASP4_ACLKX: U52.C18(mcasp4_aclkx/mcasp4_aclkr/spi3_sclk/uart8_rxd/i2c4_sda/vout2_d16/vin4a_d16/vin5a_d15)
H_MCASP4_AFSX: U52.A21(mcasp4_fsx/mcasp4_fsr/spi3_d1/uart8_txd/i2c4_scl/vout2_d17/vin4a_d17/vin5a_d14)
H_MCASP4_AXR0: U52.G16(mcasp4_axr0/spi3_d0/uart8_ctsn/uart4_rxd/vout2_d18/vin4a_d18/vin5a_d13)
H_MCASP4_AXR1: U52.D17(mcasp4_axr1/spi3_cs0/uart8_rtsn/uart4_txd/vout2_d19/vin4a_d19/vin5a_d12)
H_MCASP5_ACLKX: U52.AA3(mcasp5_aclkx/mcasp5_aclkr/spi4_sclk/uart9_rxd/i2c5_sda/mlb_clk/vout2_d20/vin4a_d20/vin5a_d11)
H_MCASP5_AFSX: U52.AB9(mcasp5_fsx/mcasp5_fsr/spi4_d1/uart9_txd/i2c5_scl/vout2_d21/vin4a_d21/vin5a_d10)
H_MCASP5_AXR0: U52.AB3(mcasp5_axr0/spi4_d0/uart9_ctsn/uart3_rxd/mlb_sig/vout2_d22/vin4a_d22/vin5a_d9)
H_MCASP5_AXR1: U52.AA4(mcasp5_axr1/spi4_cs0/uart9_rtsn/uart3_txd/mlb_dat/vout2_d23/vin4a_d23/vin5a_d8)
H_MDIO_D: R931.2 U52.U4(mdio_d/uart3_ctsn/mii0_txer/vin2a_d0/vin4b_d0/gpio5_16)
H_MDIO_D_S1: R931.1
H_MDIO_MCLK: R930.2 U52.V1(mdio_mclk/uart3_rtsn/mii0_col/vin2a_clk0/vin4b_clk1/gpio5_15)
H_MDIO_MCLK_S1: R930.1
H_MLBP_CLK_N: R184.2 TP106.1(TP) U52.AB2(MLBP_CLK_N)
H_MLBP_CLK_P: R184.1 TP105.1(TP) U52.AB1(MLBP_CLK_P)
H_MLBP_DAT_N: R183.2 TP108.1(TP) U52.AA2(MLBP_DAT_N)
H_MLBP_DAT_P: R183.1 TP107.1(TP) U52.AA1(MLBP_DAT_P)
H_MLBP_SIG_N: R182.2 TP110.1(TP) U52.AC2(MLBP_SIG_N)
H_MLBP_SIG_P: R182.1 TP109.1(TP) U52.AC1(MLBP_SIG_P)
H_MMC1_CLK: R343.1 U52.W6(mmc1_clk/gpio6_21)
H_MMC1_CMD: R344.1 U52.Y6(mmc1_cmd/gpio6_22)
H_MMC1_DAT0: R342.1 U52.AA6(mmc1_dat0/gpio6_23)
H_MMC1_DAT1: R341.1 U52.Y4(mmc1_dat1/gpio6_24)
H_MMC1_DAT2: R340.1 U52.AA5(mmc1_dat2/gpio6_25)
H_MMC1_DAT3: R345.1 U52.Y3(mmc1_dat3/gpio6_26)
H_MMC1_SD_CD: P14.9(INSERT) R327.2 U52.W7(mmc1_sdcd/uart6_rxd/i2c4_sda/gpio6_27) U131.5(IO2)
H_MMC2_CLK: R495.2 U52.J7(gpmc_a23/mmc2_clk/gpmc_a17/vin4a_fld0/vin3b_d4/gpio2_13)
H_MMC2_CLK_S1: R495.1
H_MMC2_DAT0: RN31.5(R4B) U52.J4(gpmc_a24/mmc2_dat0/gpmc_a18/vin4a_d8/vin3b_d5/gpio2_14)
H_MMC2_DAT0_S1: RN31.4(R4A)
H_MMC2_DAT1: RN31.6(R3B) U52.J6(gpmc_a25/mmc2_dat1/gpmc_a19/vin4a_d9/vin3b_d6/gpio2_15)
H_MMC2_DAT1_S1: RN31.3(R3A)
H_MMC2_DAT2: RN31.7(R2B) U52.H4(gpmc_a26/mmc2_dat2/gpmc_a20/vin4a_d10/vin3b_d7/gpio2_16)
H_MMC2_DAT2_S1: RN31.2(R2A)
H_MMC2_DAT3: RN31.8(R1B) U52.H5(gpmc_a27/mmc2_dat3/gpmc_a21/vin4a_d11/vin3b_hsync1/gpio2_17)
H_MMC2_DAT3_S1: RN31.1(R1A)
H_MMC2_DAT4: RN30.5(R4B) U52.K7(gpmc_a19/mmc2_dat4/gpmc_a13/vin4a_d12/vin3b_d0/gpio2_9)
H_MMC2_DAT4_S1: RN30.4(R4A)
H_MMC2_DAT5: RN30.6(R3B) U52.M7(gpmc_a20/mmc2_dat5/gpmc_a14/vin4a_d13/vin3b_d1/gpio2_10)
H_MMC2_DAT5_S1: RN30.3(R3A)
H_MMC2_DAT6: RN30.7(R2B) U52.J5(gpmc_a21/mmc2_dat6/gpmc_a15/vin4a_d14/vin3b_d2/gpio2_11)
H_MMC2_DAT6_S1: RN30.2(R2A)
H_MMC2_DAT7: RN30.8(R1B) U52.K6(gpmc_a22/mmc2_dat7/gpmc_a16/vin4a_d15/vin3b_d3/gpio2_12)
H_MMC2_DAT7_S1: RN30.1(R1A)
H_MMC3_CLK: R859.1 U52.AD4(mmc3_clk/usb3_ulpi_d5/vin2b_d7/vin5a_d7/ehrpwm2_tripzone_input/gpio6_29)
H_MMC3_CLK_S1: R859.2
H_MMC3_CMD: U52.AC4(mmc3_cmd/spi3_sclk/usb3_ulpi_d4/vin2b_d6/vin5a_d6/eCAP2_in_PWM2_out/gpio6_30)
H_MMC3_DAT0: U52.AC7(mmc3_dat0/spi3_d1/uart5_rxd/usb3_ulpi_d3/vin2b_d5/vin5a_d5/eQEP3A_in/gpio6_31)
H_MMC3_DAT1: U52.AC6(mmc3_dat1/spi3_d0/uart5_txd/usb3_ulpi_d2/vin2b_d4/vin5a_d4/eQEP3B_in/gpio7_0)
H_MMC3_DAT2: U52.AC9(mmc3_dat2/spi3_cs0/uart5_ctsn/usb3_ulpi_d1/vin2b_d3/vin5a_d3/eQEP3_index/gpio7_1)
H_MMC3_DAT3: U52.AC3(mmc3_dat3/spi3_cs1/uart5_rtsn/usb3_ulpi_d0/vin2b_d2/vin5a_d2/eQEP3_strobe/gpio7_2)
H_MMC3_DAT4: U52.AC8(mmc3_dat4/spi4_sclk/uart10_rxd/usb3_ulpi_nxt/vin2b_d1/vin5a_d1/ehrpwm3A/gpio1_22)
H_MMC3_DAT5: U52.AD6(mmc3_dat5/spi4_d1/uart10_txd/usb3_ulpi_dir/vin2b_d0/vin5a_d0/ehrpwm3B/gpio1_23)
H_MMC3_DAT6: U52.AB8(mmc3_dat6/spi4_d0/uart10_ctsn/usb3_ulpi_stp/vin2b_de1/vin5a_hsync0/ehrpwm3_tripzone_input/gpio1_24)
H_MMC3_DAT7: U52.AB5(mmc3_dat7/spi4_cs0/uart10_rtsn/usb3_ulpi_clk/vin2b_clk1/vin5a_vsync0/eCAP3_in_PWM3_out/gpio1_25)
H_PCIE_RXN0: U52.AG13(PCIE_RXN0)
H_PCIE_RXN1: U52.AG11(PCIE_RXN1)
H_PCIE_RXP0: U52.AH13(PCIE_RXP0)
H_PCIE_RXP1: U52.AH11(PCIE_RXP1)
H_PCIE_TXN0: U52.AG14(PCIE_TXN0)
H_PCIE_TXN1: U52.AG12(PCIE_TXN1)
H_PCIE_TXP0: U52.AH14(PCIE_TXP0)
H_PCIE_TXP1: U52.AH12(PCIE_TXP1)
H_QSPI1_D0: U52.U1(gpmc_a16/qspi1_d0/vin4a_d9/gpio2_6) ; also on sheet 22
H_QSPI1_D1: U52.P3(gpmc_a17/qspi1_d1/vin4a_d10/gpio2_7) ; also on sheet 22
H_QSPI1_D2: U52.U2(gpmc_a15/qspi1_d2/vin4a_d8/timer5/gpio2_5) ; also on sheet 22
H_QSPI1_D3: U52.T2(gpmc_a14/qspi1_d3/vin4a_vsync0/timer6/spi4_cs3/gpio2_4) ; also on sheet 22
H_QSPI1_RTCLK: U52.R3(gpmc_a13/qspi1_rtclk/vin4a_hsync0/timer7/spi4_cs2/dma_evt2/gpio2_3) ; also on sheet 22
H_QSPI1_SCLK: R963.2 U52.R2(gpmc_a18/qspi1_sclk/vin4a_d11/gpio2_8)
H_QSPI1_SCLK_S1: R963.1
H_RGMII0_RXC: R917.2 U52.U5(rgmii0_rxc/rmii1_txen/mii0_txclk/vin2a_d5/vin4b_d5/usb4_ulpi_d2/gpio5_26)
H_RGMII0_RXC_S1: R917.1
H_RGMII0_RXCTL: R918.2 U52.V5(rgmii0_rxctl/rmii1_txd1/mii0_txd3/vin2a_d6/vin4b_d6/usb4_ulpi_d3/gpio5_27)
H_RGMII0_RXCTL_S1: R918.1
H_RGMII0_RXD0: R919.2 U52.W2(rgmii0_rxd0/rmii0_txd0/mii0_txd0/vin2a_fld0/vin4b_fld1/usb4_ulpi_d7/gpio5_31)
H_RGMII0_RXD0_S1: R919.1
H_RGMII0_RXD1: R920.2 U52.Y2(rgmii0_rxd1/rmii0_txd1/mii0_txd1/vin2a_d9/usb4_ulpi_d6/gpio5_30)
H_RGMII0_RXD1_S1: R920.1
H_RGMII0_RXD2: R921.2 U52.V3(rgmii0_rxd2/rmii0_txen/mii0_txen/vin2a_d8/usb4_ulpi_d5/gpio5_29)
H_RGMII0_RXD2_S1: R921.1
H_RGMII0_RXD3: R922.2 U52.V4(rgmii0_rxd3/rmii1_txd0/mii0_txd2/vin2a_d7/vin4b_d7/usb4_ulpi_d4/gpio5_28)
H_RGMII0_RXD3_S1: R922.1
H_RGMII0_TD0: R925.2 U52.U6(rgmii0_txd0/rmii0_rxd0/mii0_rxd0/vin2a_d10/usb4_ulpi_d1/spi4_cs0/uart4_rtsn/gpio5_25)
H_RGMII0_TD0_S1: R925.1
H_RGMII0_TD1: R926.2 U52.V6(rgmii0_txd1/rmii0_rxd1/mii0_rxd1/vin2a_vsync0/vin4b_vsync1/usb4_ulpi_d0/spi4_d0/uart4_ctsn/gpio5_24)
H_RGMII0_TD1_S1: R926.1
H_RGMII0_TD2: R927.2 U52.U7(rgmii0_txd2/rmii0_rxer/mii0_rxer/vin2a_hsync0/vin4b_hsync1/usb4_ulpi_nxt/spi4_d1/uart4_txd/gpio5_23)
H_RGMII0_TD2_S1: R927.1
H_RGMII0_TD3: R928.2 U52.V7(rgmii0_txd3/rmii0_crs/mii0_crs/vin2a_de0/vin4b_de1/usb4_ulpi_dir/spi4_sclk/uart4_rxd/gpio5_22)
H_RGMII0_TD3_S1: R928.1
H_RGMII0_TXC: R923.2 U52.W9(rgmii0_txc/uart3_ctsn/rmii1_rxd1/mii0_rxd3/vin2a_d3/vin4b_d3/usb4_ulpi_clk/spi3_d0/spi4_cs2/gpio5_20)
H_RGMII0_TXC_S1: R923.1
H_RGMII0_TXCTL: R924.2 U52.V9(rgmii0_txctl/uart3_rtsn/rmii1_rxd0/mii0_rxd2/vin2a_d4/vin4b_d4/usb4_ulpi_stp/spi3_cs0/spi4_cs3/gpio5_21)
H_RGMII0_TXCTL_S1: R924.1
H_RMII_50MHZ_CLK: R929.2 U52.U3(RMII_MHZ_50_CLK/vin2a_d11/gpio5_17)
H_RMII_50MHZ_CLK_S1: R929.1
H_RSV_Y5: U52.Y5(rsv_y5)
H_SATA1_TXN0: U52.AG9(SATA1_RXP0) U52.AG10(SATA1_TXN0) U52.AG15(LJCB_CLKP)
H_SATA1_TXP0: U52.AH9(SATA1_RXN0) U52.AH10(SATA1_TXP0)
H_USB1_DM: U52.AC12(USB1_DM) ; also on sheet 32
H_USB1_DP: U52.AD12(USB1_DP) ; also on sheet 32
H_USB1_DRV_VBUS: U52.AB10(USB1_DRVVBUS) ; also on sheet 32
H_USB2_DM: U52.AF11(USB2_DM) ; also on sheet 33
H_USB2_DP: U52.AE11(USB2_DP) ; also on sheet 33
H_USB2_DRV_VBUS: U52.AC10(USB2_DRVVBUS) ; also on sheet 33
H_VIN1A_CLK0: R961.2 U52.AG8(vin1a_clk0/vout3_d16/vout3_fld/gpio2_30)
H_VIN1A_CLK0_S1: R961.1
H_VIN1A_D0: U52.AE8(vin1a_d0/vout3_d7/vout3_d23/uart8_rxd/ehrpwm1A/gpio3_4)
H_VIN1A_D1: U52.AD8(vin1a_d1/vout3_d6/vout3_d22/uart8_txd/ehrpwm1B/gpio3_5)
H_VIN1A_D2: U52.AG7(vin1a_d2/vout3_d5/vout3_d21/uart8_ctsn/ehrpwm1_tripzone_input/gpio3_6)
H_VIN1A_D3: U52.AH6(vin1a_d3/vout3_d4/vout3_d20/uart8_rtsn/eCAP1_in_PWM1_out/gpio3_7)
H_VIN1A_D4: U52.AH3(vin1a_d4/vout3_d3/vout3_d19/ehrpwm1_synci/gpio3_8)
H_VIN1A_D5: U52.AH5(vin1a_d5/vout3_d2/vout3_d18/ehrpwm1_synco/gpio3_9)
H_VIN1A_D6: U52.AG6(vin1a_d6/vout3_d1/vout3_d17/eQEP2A_in/gpio3_10)
H_VIN1A_D7: U52.AH4(vin1a_d7/vout3_d0/vout3_d16/eQEP2B_in/gpio3_11)
H_VIN1A_D8: U52.AG4(vin1a_d8/vin1b_d7/vout3_d15/kbd_row2/eQEP2_index/gpio3_12)
H_VIN1A_D9: U52.AG2(vin1a_d9/vin1b_d6/vout3_d14/kbd_row3/eQEP2_strobe/gpio3_13)
H_VIN1A_D10: U52.AG3(vin1a_d10/vin1b_d5/vout3_d13/kbd_row4/gpio3_14)
H_VIN1A_D11: U52.AG5(vin1a_d11/vin1b_d4/vout3_d12/gpmc_a23/kbd_row5/gpio3_15)
H_VIN1A_D12: U52.AF2(vin1a_d12/vin1b_d3/usb3_ulpi_d7/vout3_d11/gpmc_a24/kbd_row6/gpio3_16)
H_VIN1A_D13: U52.AF6(vin1a_d13/vin1b_d2/usb3_ulpi_d6/vout3_d10/gpmc_a25/kbd_row7/gpio3_17)
H_VIN1A_D14: U52.AF3(vin1a_d14/vin1b_d1/usb3_ulpi_d5/vout3_d9/gpmc_a26/kbd_row8/gpio3_18)
H_VIN1A_D15: U52.AF4(vin1a_d15/vin1b_d0/usb3_ulpi_d4/vout3_d8/gpmc_a27/kbd_col0/gpio3_19)
H_VIN1A_D16: U52.AF1(vin1a_d16/vin1b_d7/usb3_ulpi_d3/vout3_d7/vin3a_d0/kbd_col1/gpio3_20)
H_VIN1A_D17: U52.AE3(vin1a_d17/vin1b_d6/usb3_ulpi_d2/vout3_d6/vin3a_d1/kbd_col2/gpio3_21)
H_VIN1A_D18: U52.AE5(vin1a_d18/vin1b_d5/usb3_ulpi_d1/vout3_d5/vin3a_d2/kbd_col3/gpio3_22)
H_VIN1A_D19: U52.AE1(vin1a_d19/vin1b_d4/usb3_ulpi_d0/vout3_d4/vin3a_d3/kbd_col4/gpio3_23)
H_VIN1A_D20: U52.AE2(vin1a_d20/vin1b_d3/usb3_ulpi_nxt/vout3_d3/vin3a_d4/kbd_col5/gpio3_24)
H_VIN1A_D21: U52.AE6(vin1a_d21/vin1b_d2/usb3_ulpi_dir/vout3_d2/vin3a_d5/kbd_col6/gpio3_25)
H_VIN1A_D22: U52.AD2(vin1a_d22/vin1b_d1/usb3_ulpi_stp/vout3_d1/vin3a_d6/kbd_col7/gpio3_26)
H_VIN1A_D23: U52.AD3(vin1a_d23/vin1b_d0/usb3_ulpi_clk/vout3_d0/vin3a_d7/kbd_col8/gpio3_27)
H_VIN1A_DE0: U52.AD9(vin1a_de0/vin1b_hsync1/vout3_d17/vout3_de/uart7_rxd/timer16/spi3_sclk/kbd_row0/eQEP1A_in/gpio3_0)
H_VIN1A_FLD0: U52.AF9(vin1a_fld0/vin1b_vsync1/vout3_clk/uart7_txd/timer15/spi3_d1/kbd_row1/eQEP1B_in/gpio3_1)
H_VIN1A_HSYNC0: U52.AE9(vin1a_hsync0/vin1b_fld1/vout3_hsync/uart7_ctsn/timer14/spi3_d0/eQEP1_index/gpio3_2)
H_VIN1A_VSYNC0: U52.AF8(vin1a_vsync0/vin1b_de1/vout3_vsync/uart7_rtsn/timer13/spi3_cs0/eQEP1_strobe/gpio3_3)
H_VIN1B_CLK1: R960.2 U52.AH7(vin1b_clk1/vin3a_clk0/gpio2_31)
H_VIN1B_CLK1_S1: R960.1
H_VIN2A_CLK0: R962.2 U52.E1(vin2a_clk0/vout2_fld/emu5/kbd_row0/eQEP1A_in/gpio3_28)
H_VIN2A_CLK0_S1: R962.1
H_VIN2A_D0: U52.F2(vin2a_d0/vout2_d23/emu10/uart9_ctsn/spi4_d0/kbd_row4/ehrpwm1B/gpio4_1)
H_VIN2A_D1: U52.F3(vin2a_d1/vout2_d22/emu11/uart9_rtsn/spi4_cs0/kbd_row5/ehrpwm1_tripzone_input/gpio4_2)
H_VIN2A_D2: U52.D1(vin2a_d2/vout2_d21/emu12/uart10_rxd/kbd_row6/eCAP1_in_PWM1_out/gpio4_3)
H_VIN2A_D3: U52.E2(vin2a_d3/vout2_d20/emu13/uart10_txd/kbd_col0/ehrpwm1_synci/gpio4_4)
H_VIN2A_D4: U52.D2(vin2a_d4/vout2_d19/emu14/uart10_ctsn/kbd_col1/ehrpwm1_synco/gpio4_5)
H_VIN2A_D5: U52.F4(vin2a_d5/vout2_d18/emu15/uart10_rtsn/kbd_col2/eQEP2A_in/gpio4_6)
H_VIN2A_D6: U52.C1(vin2a_d6/vout2_d17/emu16/mii1_rxd1/kbd_col3/eQEP2B_in/gpio4_7)
H_VIN2A_D7: U52.E4(vin2a_d7/vout2_d16/emu17/mii1_rxd2/kbd_col4/eQEP2_index/gpio4_8)
H_VIN2A_D8: U52.F5(vin2a_d8/vout2_d15/emu18/mii1_rxd3/kbd_col5/eQEP2_strobe/gpio4_9)
H_VIN2A_D9: U52.E6(vin2a_d9/vout2_d14/emu19/mii1_rxd0/kbd_col6/ehrpwm2A/gpio4_10)
H_VIN2A_D10: U52.D3(vin2a_d10/mdio_mclk/vout2_d13/kbd_col7/ehrpwm2B/gpio4_11)
H_VIN2A_D11: U52.F6(vin2a_d11/mdio_d/vout2_d12/kbd_row7/ehrpwm2_tripzone_input/gpio4_12)
H_VIN2A_D12: U52.D5(vin2a_d12/rgmii1_txc/vout2_d11/mii1_rxclk/kbd_col8/eCAP2_in_PWM2_out/gpio4_13)
H_VIN2A_D13: U52.C2(vin2a_d13/rgmii1_txctl/vout2_d10/mii1_rxdv/kbd_row8/eQEP3A_in/gpio4_14)
H_VIN2A_D14: U52.C3(vin2a_d14/rgmii1_txd3/vout2_d9/mii1_txclk/eQEP3B_in/gpio4_15)
H_VIN2A_D15: U52.C4(vin2a_d15/rgmii1_txd2/vout2_d8/mii1_txd0/eQEP3_index/gpio4_16)
H_VIN2A_D16: U52.B2(vin2a_d16/vin2b_d7/rgmii1_txd1/vout2_d7/vin3a_d8/mii1_txd1/eQEP3_strobe/gpio4_24)
H_VIN2A_D17: U52.D6(vin2a_d17/vin2b_d6/rgmii1_txd0/vout2_d6/vin3a_d9/mii1_txd2/ehrpwm3A/gpio4_25)
H_VIN2A_D18: U52.C5(vin2a_d18/vin2b_d5/rgmii1_rxc/vout2_d5/vin3a_d10/mii1_txd3/ehrpwm3B/gpio4_26)
H_VIN2A_D19: U52.A3(vin2a_d19/vin2b_d4/rgmii1_rxctl/vout2_d4/vin3a_d11/mii1_txer/ehrpwm3_tripzone_input/gpio4_27)
H_VIN2A_D20: U52.B3(vin2a_d20/vin2b_d3/rgmii1_rxd3/vout2_d3/vin3a_de0/vin3a_d12/mii1_rxer/eCAP3_in_PWM3_out/gpio4_28)
H_VIN2A_D21: U52.B4(vin2a_d21/vin2b_d2/rgmii1_rxd2/vout2_d2/vin3a_fld0/vin3a_d13/mii1_col/gpio4_29)
H_VIN2A_D22: U52.B5(vin2a_d22/vin2b_d1/rgmii1_rxd1/vout2_d1/vin3a_hsync0/vin3a_d14/mii1_crs/gpio4_30)
H_VIN2A_D23: U52.A4(vin2a_d23/vin2b_d0/rgmii1_rxd0/vout2_d0/vin3a_vsync0/vin3a_d15/mii1_txen/gpio4_31)
H_VIN2A_DE0: U52.G2(vin2a_de0/vin2a_fld0/vin2b_fld1/vin2b_de1/vout2_de/emu6/kbd_row1/eQEP1B_in/gpio3_29)
H_VIN2A_FLD0: U52.H7(vin2a_fld0/vin2b_clk1/vout2_clk/emu7/eQEP1_index/gpio3_30)
H_VIN2A_HSYNC0: U52.G1(vin2a_hsync0/vin2b_hsync1/vout2_hsync/emu8/uart9_rxd/spi4_sclk/kbd_row2/eQEP1_strobe/gpio3_31)
H_VIN2A_VSYNC0: U52.G6(vin2a_vsync0/vin2b_vsync1/vout2_vsync/emu9/uart9_txd/spi4_d1/kbd_row3/ehrpwm1A/gpio4_0)
H_XREF_CLK0: U52.D18(xref_clk0/mcasp2_axr8/mcasp1_axr4/mcasp1_ahclkx/mcasp5_ahclkx/atl_clk0/vin6a_d0/hdq0/clkout2/timer13/gpio6_17)
H_XREF_CLK1: U52.E17(xref_clk1/mcasp2_axr9/mcasp1_axr5/mcasp2_ahclkx/mcasp6_ahclkx/atl_clk1/vin6a_clk0/timer14/gpio6_18)
H_XREF_CLK2: U52.B26(ref_clk2/mcasp2_axr10/mcasp1_axr5/mcasp3_ahclkx/mcasp7_ahclkx/atl_clk2/vout2_clk/vin4a_clk0/timer15/gpio6_19)
H_XREF_CLK3: U52.C23(xref_clk3/mcasp2_axr11/mcasp1_axr7/mcasp4_ahclkx/mcasp8_ahclkx/atl_clk3/vout2_de/hdq0/vin4a_de0/clkout3/timer16/gpio6_20)
VEVM_3V3: R14.1 R15.1 R16.1 R17.1 R18.1 R19.1 R327.1 R758.1 R759.1 R774.1 R828.1 R829.1 ; also on sheet 13 21 22 31 32 33 34 35 37 38 40 41 42 43 44 45 46 48 49 51 52 55 56 57
VEVM_3V3_SD: C14.1 C15.1 C16.1 C233.1 C693.1 C787.1 P14.4(VDD) R774.2 U77.1(VCC) U78.1(VCC) U79.1(VCC) U131.1(VCC)
VOUT1_D2: J17.13(TR_CLK0) ; also on sheet 37 58
VOUT1_D3: J17.25(TRD0.4) ; also on sheet 37 58
VOUT1_D4: J17.27(TRD0.5) ; also on sheet 37 58
VOUT1_D5: J17.29(TRD0.6) ; also on sheet 37 58
VOUT1_D6: J17.31(TRD0.7) ; also on sheet 37 58
VOUT1_D10: J17.17(TRD0.0) ; also on sheet 37 58
VOUT1_D11: J17.35(TRD0.9) ; also on sheet 37 58
VOUT1_D12: J17.37(TRD3.0) ; also on sheet 37 58
VOUT1_D13: J17.39(TRD3.1) ; also on sheet 37 58
VOUT1_D14: J17.41(TRD3.2) ; also on sheet 37 58
VOUT1_D15: J17.43(TRD3.3) ; also on sheet 37 58
VOUT1_D18: J17.23(TRD0.3) ; also on sheet 37 58
VOUT1_D19: J17.45(TRD3.4) ; also on sheet 37 58
VOUT1_D20: J17.47(TRD3.5) ; also on sheet 37 58
VOUT1_D21: J17.49(TRD3.6) ; also on sheet 37 58
VOUT1_D22: J17.51(TRD3.7) ; also on sheet 37 58
VOUT1_D23: J17.53(TRD3.8) ; also on sheet 37 58
VOUT_D7: J17.33(TRD0.8) ; also on sheet 37
VREF_DBG: J17.1(VREF_DBG) J17.12(VREF_TR) R758.2
VUSB_3V3: C439.1 C440.1 C451.1 C489.1 U52.AA12(VDDA33V_USB1) U52.Y12(VDDA33V_USB2) ; also on sheet 41
N19060121: J17.15(TGT_DETECT) R762.2
N22728109: P14.10(INSERT_COM) R964.1

Not connected (* = marked no-connect by the designer): J17 6(nRESET)* 10(EXTE)* 11(EXTF)* 14(TR_CLK1)* 18(TRD1.0)* 20(TRD1.1)* 22(TRD1.2)* 24(TRD1.3)* 26(TRD1.4)* 28(TRD1.5)* 30(TRD1.6)* 32(TRD1.7)* 34(TRD1.8)* 36(TRD1.9)* 38(TRD2.0)* 40(TRD2.1)* 42(TRD2.2)* 44(TRD2.3)* 46(TRD2.4)* 48(TRD2.5)* 50(TRD2.6)* 52(TRD2.7)* 54(TRD2.8)* 55(TRD3.9)* 56(TRD2.9)* 59(TR_CLK3)* 60(TR_CLK2)*; P14 11 12 13 14 15; U52 AC11(USB_TXN0) AD11(USB_TXP0) AE12(USB_RXP0) AF12(USB_RXN0); U77 2(NC.2); U78 2(NC.2); U79 2(NC.2); U131 2(NC.2) 3(IO1)

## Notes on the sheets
sheet 1
- TI CONFIDENTIAL - NDA RESTRICTIONS
- SH01 - TITLE PAGE
  SH02 - VAYU MCASP
  SH03 - VAYU SERIAL I/O
  SH04 - VAYU SD/MMC
  SH05 - VAYU ETHERNET
  SH06 - VAYU USB
  SH07 - VAYU GPMC
  SH08 - VAYU DDR EMIF1
  SH09 - VAYU DDR EMIF2
  SH10 - VAYU HDMI MLB
  SH11 - VAYU VOUT1/LCD PORT
  SH12 - VAYU VIDEO INPUT PORTS
  SH13 - VAYU SATA/PCIe
  SH14 - VAYU JTAG TRACE
  SH15 - VAYU CLOCKS
  SH16 - VAYU INTERNAL LDOS
  SH17 - VAYU IO POWER
  SH18 - VAYU 1V8 DIGITAL POWER
  SH19 - VAYU DDR POWER
  SH20 - VAYU 1V8 ANALOG POWER
  SH21 - VAYU AVS POWER
  SH22 - VAYU GROUND
- SH23 - eMMC Memory
  SH24 - SPI Flash
  SH25 - Blank
  SH26 - DDR3 EMIF1 TESTPOINTS
  SH27 - DDR3  EMIF1 BANK 1
  SH28 - DDR3 EMIF1 CAPS
  SH29 - DDR3 BANK1 TERM
  SH30 - DDR3  EMIF2 TESTPOINTS
  SH31 - DDR3 EMIF2 BANK 2
  SH32 - DDR3 EMIF2 CAPS
  SH33 - DDR EMIF2 TERM
  SH34 - USB1
  SH35 - USB2
  SH36 - COM8 LEVEL TRANSLATOR
  SH37 - COM8 CONNECTOR
  SH38 - COM8 POWER
  SH39 - CAN/LIN
  SH40 - VIDEO OUT FPD LINK
  SH41 - VIDEO IN
  SH42 - AUDIO CO-DEC
  SH43 - PMIC CONTROL
  SH44 - PMIC LDOs
  SH45 - PMIC SMPS1-5
  SH46 - PMIC SMPS6-9 INT POWER
- SH47 - RESET GENERATION
  SH48 - SOC BOOT SETTINGS
  SH49 - DEBUG
  SH50 - BD POWER INPUT
  SH51 - BD POWER PRIMARY CONVERTER
  SH52 - BD POWER 3V3 SWITCHED
  SH53 - BD POWER VTT DDR3 TERM
  SH54 - BD POWER 1V35 DDR3 CORE
  SH55 - BD EEPROM TEMP IPOD
  SH56 - REV HISTORY
- Work - In - Progress
- REVISION STATUS OF SHEETS
- REV
- B
- SH
- 99
- REV
- SH
- REV
- SH
- REV
- SH
- REV
- A
- A
- A
- A
- A
- SH
- 51
- 52
- 53
- 54
- 55
- REV
- A
- A
- A
- A
- A
- A
- A
- A
- A
- A
- SH
- 41
- 42
- 43
- 44
- 45
- 46
- 47
- 48
- 49
- 50
- REV
- A
- A
- A
- A
- A
- A
- A
- A
- A
- A
- DWN
- DATE
- SH
- 31
- 32
- 33
- 34
- 35
- 36
- 37
- 38
- 39
- 40
- REV
- B
- A
- A
- A
- A
- A
- A
- A
- A
- A
- CHK
- DATE
- ENGR
- DATE
- SH
- 21
- 22
- 23
- 24
- 25
- 26
- 27
- 28
- 29
- 30
- ENGR-MGR
- DATE
- REV
- A
- A
- A
- A
- A
- A
- A
- A
- B
- A
- SH
- 11
- 12
- 13
- 14
- 15
- 16
- 17
- 18
- 19
- 20
- QA
- DATE
- MFG
- DATE
- REV
- B
- A
- A
- A
- A
- A
- A
- A
- A
- A
- NEXT ASSY
- USED ON
- Preliminary Information - Subject to change
- RLSE
- DATE
- SH
- 1
- 2
- 3
- 4
- 5
- 6
- 7
- 8
- 9
- 10
- APPLICATION
sheet 2
- TI CONFIDENTIAL - NDA RESTRICTIONS
- Work - In - Progress
- Preliminary Information - Subject to change
sheet 3
- CAPACITANCE      Commerical     Automotive
  Vaule            Size/X5R       Size/X7R
  .1uF             0201           0402
  .22uF            0201           0603
  .47uF            0201           0603
  1uF              0201           0603
  2.2uF            0402           0603
  4.7uF            0402           0805
  10uF             0402           0805
  22uF             0603           1206
- TI CONFIDENTIAL - NDA RESTRICTIONS
- Auto Cap Sizes Updated
- Work - In - Progress
- Preliminary Information - Subject to change
sheet 4
- TI CONFIDENTIAL - NDA RESTRICTIONS
- Work - In - Progress
- Preliminary Information - Subject to change
sheet 5
- TI CONFIDENTIAL - NDA RESTRICTIONS
- Auto Cap Sizes Updated
- 3.3 VOLT
- 1.8 VOLT
- DIFFERENTIAL PAIR
  90 OHM DIFFERENTIAL
  IMPEDANCE
  SHORT AND STRAIGHT AS
  POSSIBLE,
  MINIMUM NUMBER OF VIAS
- Work - In - Progress
- CAPACITANCE      Commerical     Automotive
  Vaule            Size/X5R       Size/X7R
  .1uF             0201           0402
  .22uF            0201           0603
  .47uF            0201           0603
  1uF              0201           0603
  2.2uF            0402           0603
  4.7uF            0402           0805
  10uF             0402           0805
  22uF             0603           1206
- Preliminary Information - Subject to change
sheet 6
- TI CONFIDENTIAL - NDA RESTRICTIONS
- Work - In - Progress
- PCB Matched Group = H_QSPI_xxx
- Preliminary Information - Subject to change
sheet 7
- EACH DATA GROUP IS MATCHED WITHIN THE GROUP
- TI CONFIDENTIAL - NDA RESTRICTIONS
- Auto Cap Sizes Updated
- USE 4X SPACING TRACE-TO-TRACE;
  "FLIGHT-TIME MATCHING" PREFERRED
  OVER "LENGTH MATCHING.
- differential pairs 100 ohm
- 6 places
- Data Group 0-0
- Data Group 0-1
- Work - In - Progress
- Data Group 0-2
- Data Group 0-3
- CAPACITANCE      Commerical     Automotive
  Vaule            Size/X5R       Size/X7R
  .1uF             0201           0402
  .22uF            0201           0603
  .47uF            0201           0603
  1uF              0201           0603
  2.2uF            0402           0603
  4.7uF            0402           0805
  10uF             0402           0805
  22uF             0603           1206
- Preliminary Information - Subject to change
sheet 8
- TI CONFIDENTIAL - NDA RESTRICTIONS
- EACH DATA GROUP IS MATCHED WITHIN THE GROUP
- USE 4X SPACING TRACE-TO-TRACE;
  "FLIGHT-TIME MATCHING" PREFERRED
  OVER "LENGTH MATCHING.
- differential pairs 100 ohm
- Auto Cap Sizes Updated
- Work - In - Progress
- 5 places
- Data Group 2-0
- CONTROL GROUP 2
- Data Group 2-1
- Data Group 2-2
- Data Group 2-3
- CLOCK GROUP 2
- DDR2_RST is not part of group
- VDDR_VREFSSTL is not part of group
- WARNING [DRC0006]   Net has fewer than two connections N23667068:  VAYU_EVM, SH26 - VAYU DDR EMIF2 INTERFACE  (3.20, 4.00)
  WARNING [DRC0006]   Net has fewer than two connections N23667055:  VAYU_EVM, SH26 - VAYU DDR EMIF2 INTERFACE  (3.20, 2.40)
  WARNING [DRC0006]   Net has fewer than two connections N25725225:  VAYU_EVM, SH25 - VAYU DDR EMIF1 INTERFACE  (3.10, 3.50)
  WARNING [DRC0006]   Net has fewer than two connections N25725223:  VAYU_EVM, SH25 - VAYU DDR EMIF1 INTERFACE  (3.10, 2.20)
- CAPACITANCE      Commerical     Automotive
  Vaule            Size/X5R       Size/X7R
  .1uF             0201           0402
  .22uF            0201           0603
  .47uF            0201           0603
  1uF              0201           0603
  2.2uF            0402           0603
  4.7uF            0402           0805
  10uF             0402           0805
  22uF             0603           1206
- Preliminary Information - Subject to change
sheet 9
- TI CONFIDENTIAL - NDA RESTRICTIONS
- Auto Cap Sizes Updated
- Work - In - Progress
- 1.8 VOLT
- DIFFERENTIAL PAIR
  90 OHM DIFFERENTIAL
  IMPEDANCE
  SHORT AND STRAIGHT AS
  POSSIBLE,
  MINIMUM NUMBER OF VIAS
- 100 ohm diff pairs
- PLACE 100 OHM RESISTORS AT CPU
- CAPACITANCE      Commerical     Automotive
  Vaule            Size/X5R       Size/X7R
  .1uF             0201           0402
  .22uF            0201           0603
  .47uF            0201           0603
  1uF              0201           0603
  2.2uF            0402           0603
  4.7uF            0402           0805
  10uF             0402           0805
  22uF             0603           1206
- Preliminary Information - Subject to change
sheet 10
- TI CONFIDENTIAL - NDA RESTRICTIONS
- Work - In - Progress
- Preliminary Information - Subject to change
sheet 11
- TI CONFIDENTIAL - NDA RESTRICTIONS
- 1.8 VOLT
- Auto Cap Sizes Updated
- 1.8 VOLT
- Work - In - Progress
- DIFFERENTIAL PAIR
  90 OHM DIFFERENTIAL
  IMPEDANCE
  SHORT AND STRAIGHT AS
  POSSIBLE,
  MINIMUM NUMBER OF VIAS
- CAPACITANCE      Commerical     Automotive
  Vaule            Size/X5R       Size/X7R
  .1uF             0201           0402
  .22uF            0201           0603
  .47uF            0201           0603
  1uF              0201           0603
  2.2uF            0402           0603
  4.7uF            0402           0805
  10uF             0402           0805
  22uF             0603           1206
- Preliminary Information - Subject to change
sheet 12
- TI CONFIDENTIAL - NDA RESTRICTIONS
- Work - In - Progress
- TRSTn ==  MIPI TRSTPD PULL DOWN VERSION
  TRSTn ==  MIPI nTRST MIPI PULLUP VERSION
  FOR CJTAG REMOVE R761 AND POPULATE R760,
  AS CTJAG NEEDS THE PULLUP VERSION.
- Preliminary Information - Subject to change
